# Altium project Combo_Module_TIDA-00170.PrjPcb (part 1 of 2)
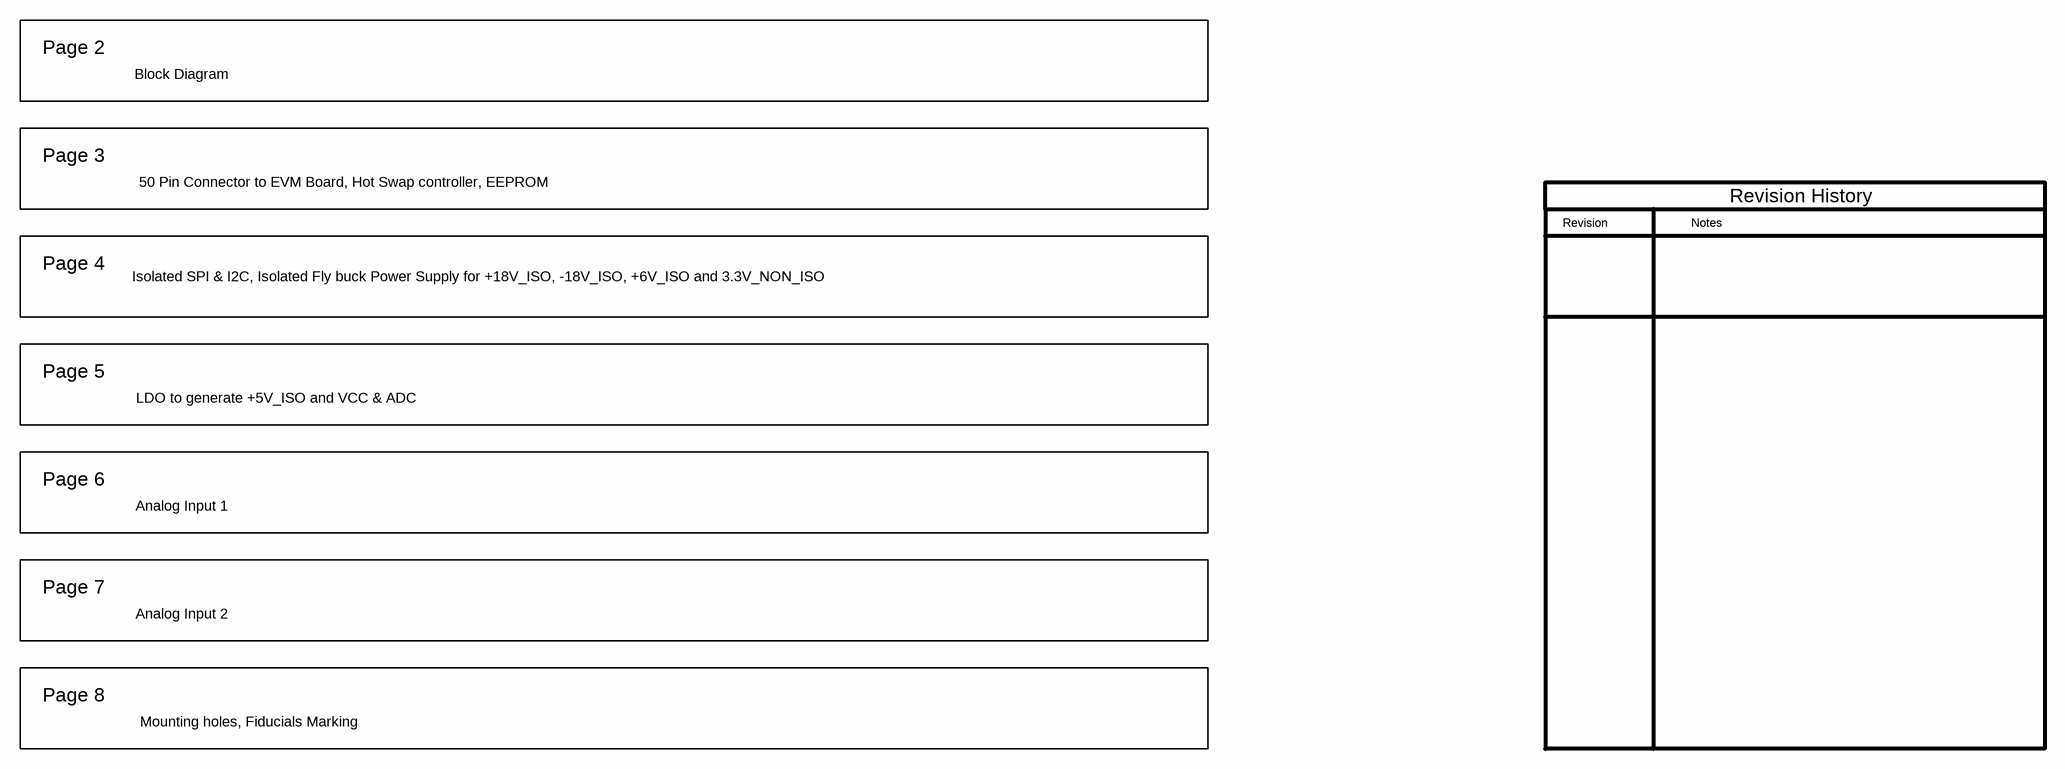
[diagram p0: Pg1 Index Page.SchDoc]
CopyrightYear: 2014; PCB_Rev: E1; PRJ_Customer: Public Release; PRJ_Engineer: Amol Gadkari; PRJ_Number: TIDA-00170; PRJ_Title: Analog Input Output Module; SCH_Rev: E1; TechSupport: http://www.ti.com/support
8 sheets, 276 parts. Net scope: flat (ports and power ports of the same name join across sheets).
Board file: TIDA-00170.PcbDoc
Sheets:
  Pg1 Index Page.SchDoc
  Pg2 Block Diagram.SchDoc
  Pg3 Interboard conn, HS & EEPROM.SchDoc
  Pg4 ISO Power Supply, I2C & SPI Isolators.SchDoc
  Pg5 LDO.SchDoc
  Pg6 ADC.SchDoc
  Pg8 Analog Output.SchDoc
  Pg9 Hardware.SchDoc

## Sheet Pg1 Index Page.SchDoc
size 431 x 279 mm; Date: Not shown in title block; ApprovedBy: Not shown in title block; CheckedBy: Not shown in title block; Author: Not shown in title block; CompanyName: Not shown in title block; Engineer: Not shown in title block; Organization: Not shown in title block; Address1: Not shown in title block; Address2: Not shown in title block; Address3: Not shown in title block; Address4: Not shown in title block; DocumentNumber: 1; Revision: Use project parameter SCH_Rev; SheetNumber: 1; SheetTotal: 8; PageSetup: Record=PageOptions|CenterHorizontal=True|CenterVertical=True|PrintScale=0.62|XCorrection=1.00|YCorrection=1.00|PrintKind=0|BorderSize=5000000|LeftOffset=0|BottomOffset=0|Orientation=2|PaperLength=1000|PaperWidth=1000|Scale=100|PaperSource=15|PrintQuality=600|MediaType=1|DitherType=10|PaperKind=Letter|PrintScaleMode=1

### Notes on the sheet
- Page 2
- Block Diagram
- Page 3
- 50 Pin Connector to EVM Board, Hot Swap controller, EEPROM
- Revision History
- Page 4
- Revision
- Notes
- Isolated SPI & I2C, Isolated Fly buck Power Supply for +18V_ISO, -18V_ISO, +6V_ISO and 3.3V_NON_ISO
- Page 5
- LDO to generate +5V_ISO and VCC & ADC
- Page 6
- Analog Input 1
- Page 7
- Analog Input 2
- Page 8
- Mounting holes, Fiducials Marking

## Sheet Pg2 Block Diagram.SchDoc
size 431 x 279 mm; Date: Not shown in title block; ApprovedBy: Not shown in title block; CheckedBy: Not shown in title block; Author: Not shown in title block; CompanyName: Not shown in title block; Engineer: Not shown in title block; Organization: Not shown in title block; Address1: Not shown in title block; Address2: Not shown in title block; Address3: Not shown in title block; Address4: Not shown in title block; DocumentNumber: 2; Revision: Use project parameter SCH_Rev; SheetNumber: 2; SheetTotal: 8; PageSetup: Record=PageOptions|CenterHorizontal=True|CenterVertical=True|PrintScale=1.00|XCorrection=1.00|YCorrection=1.00|PrintKind=0|BorderSize=5000000|LeftOffset=0|BottomOffset=0|Orientation=2|PaperLength=1000|PaperWidth=1000|Scale=100|PaperSource=15|PrintQuality=600|MediaType=1|DitherType=10|PaperKind=Letter|PrintScaleMode=1
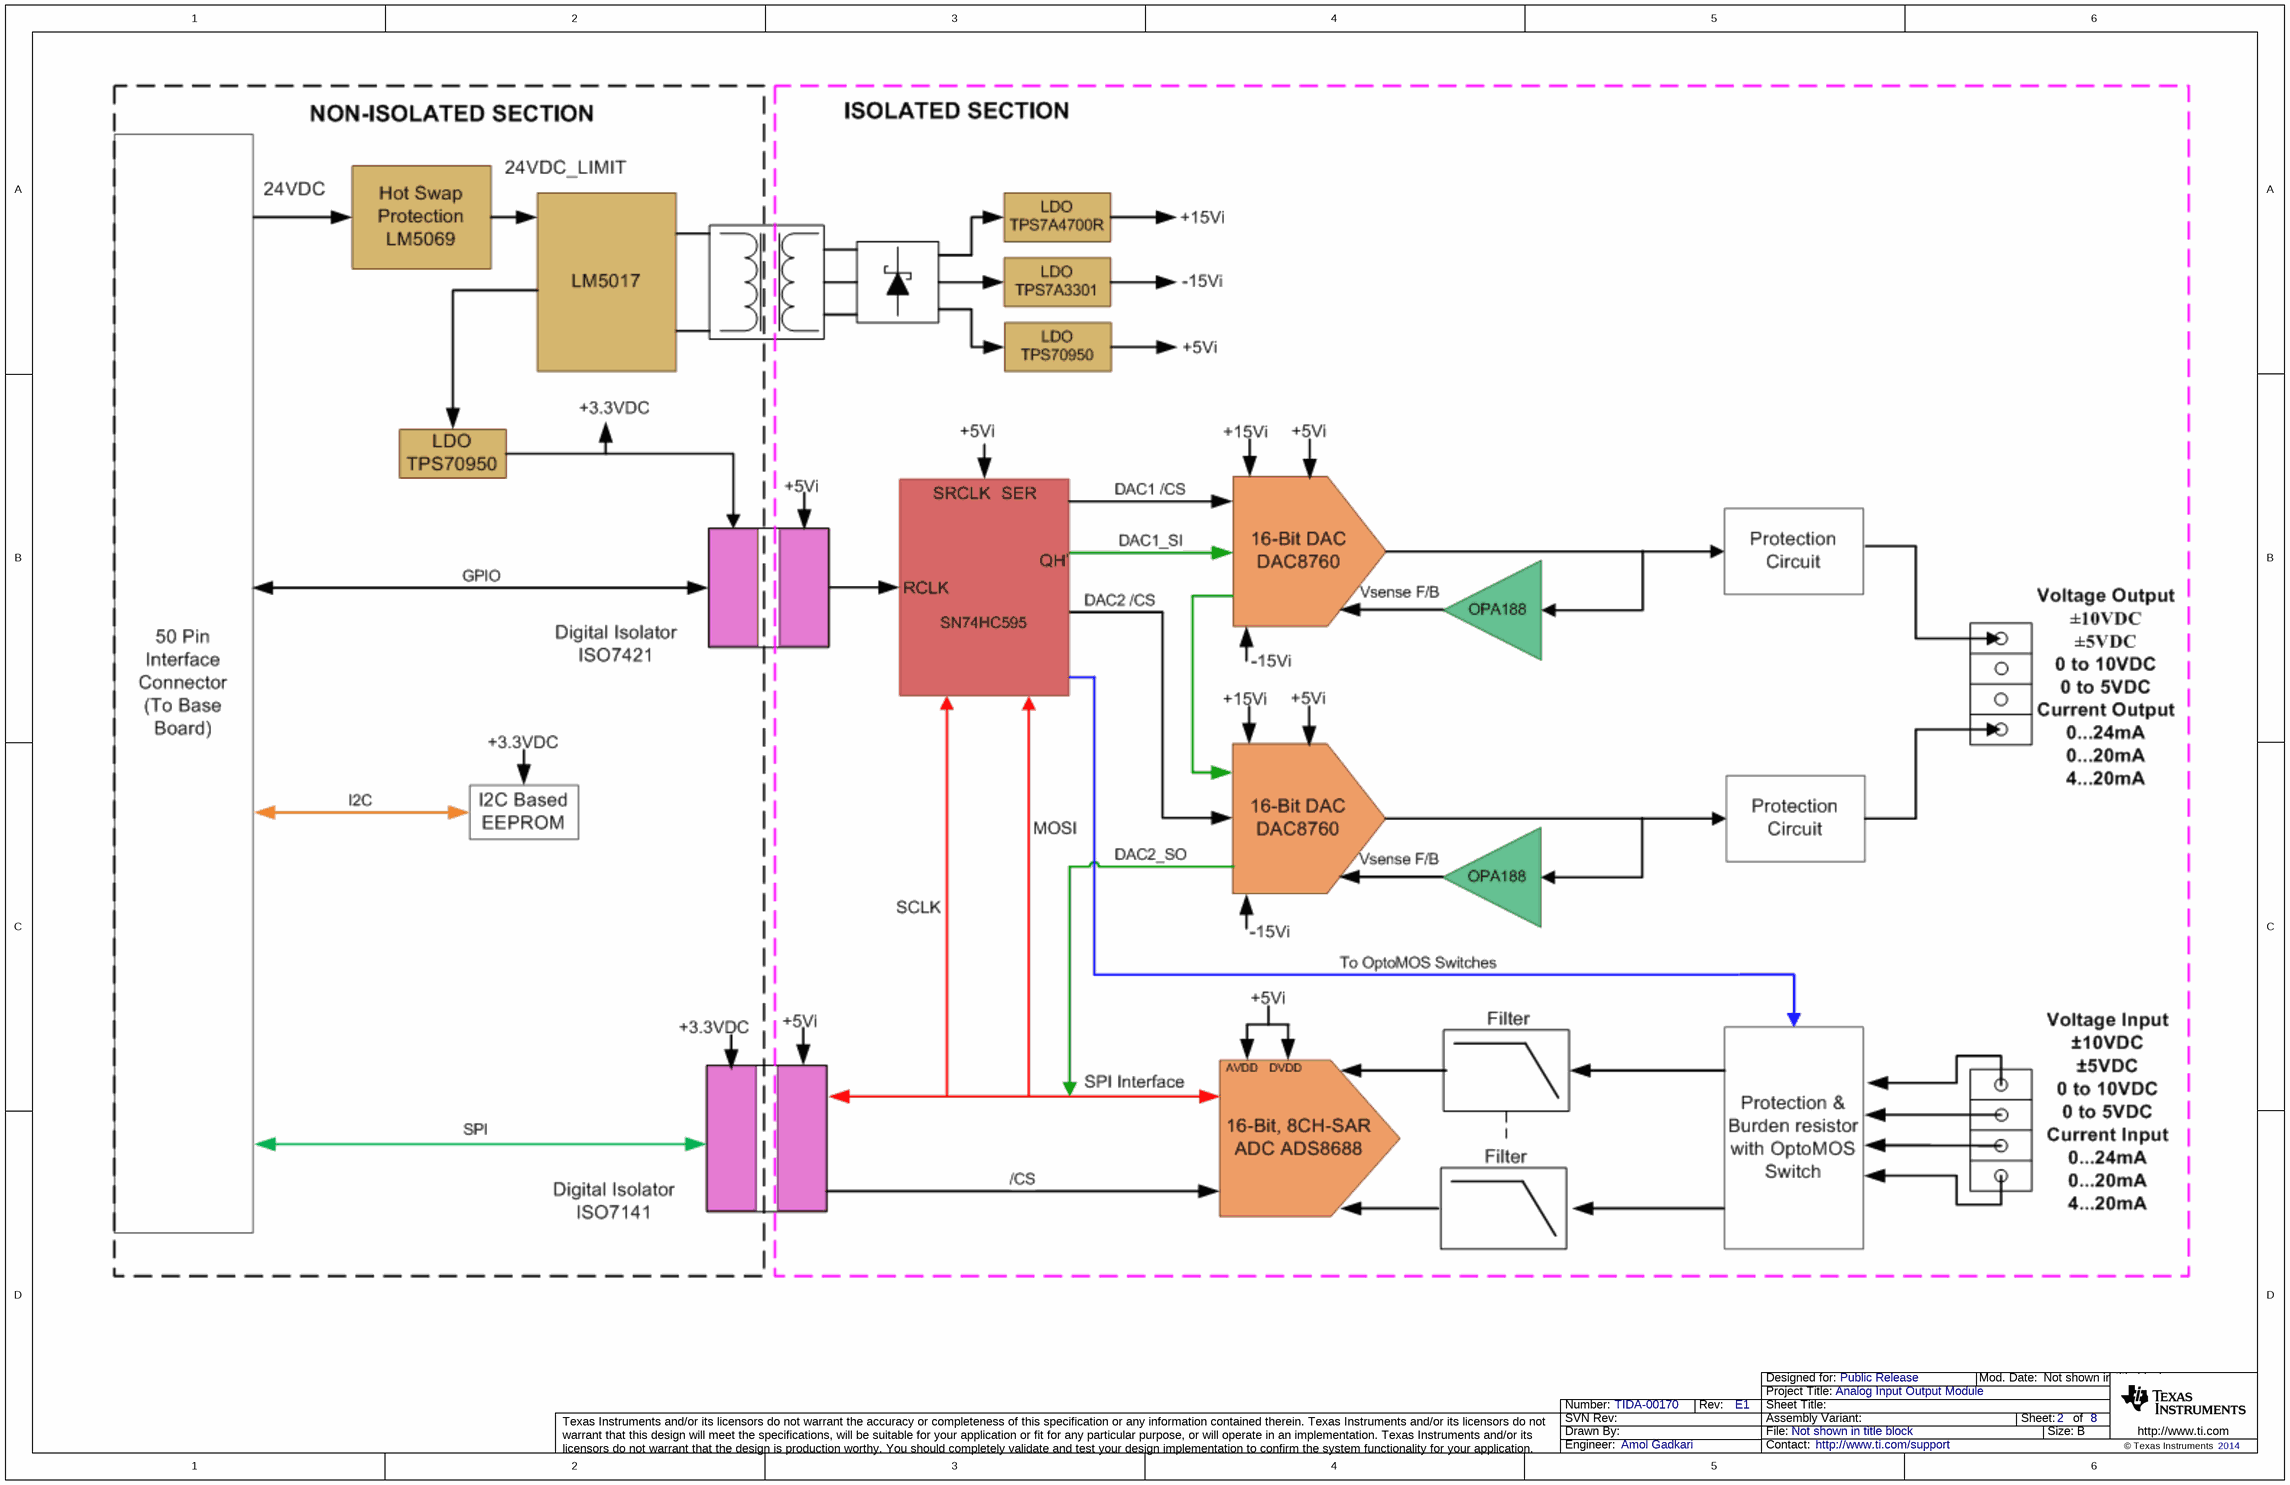
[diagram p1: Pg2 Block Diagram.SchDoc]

## Sheet Pg3 Interboard conn, HS & EEPROM.SchDoc
size 431 x 279 mm; Date: Not shown in title block; ApprovedBy: Not shown in title block; CheckedBy: Not shown in title block; Author: Not shown in title block; CompanyName: Not shown in title block; Engineer: Not shown in title block; Organization: Not shown in title block; Address1: Not shown in title block; Address2: Not shown in title block; Address3: Not shown in title block; Address4: Not shown in title block; DocumentNumber: 3; Revision: Use project parameter SCH_Rev; SheetNumber: 3; SheetTotal: 8; PageSetup: Record=PageOptions|CenterHorizontal=True|CenterVertical=True|PrintScale=1.00|XCorrection=1.00|YCorrection=1.00|PrintKind=0|BorderSize=5000000|LeftOffset=0|BottomOffset=0|Orientation=2|PaperLength=1000|PaperWidth=1000|Scale=100|PaperSource=15|PrintQuality=600|MediaType=1|DitherType=10|PaperKind=Letter|PrintScaleMode=1
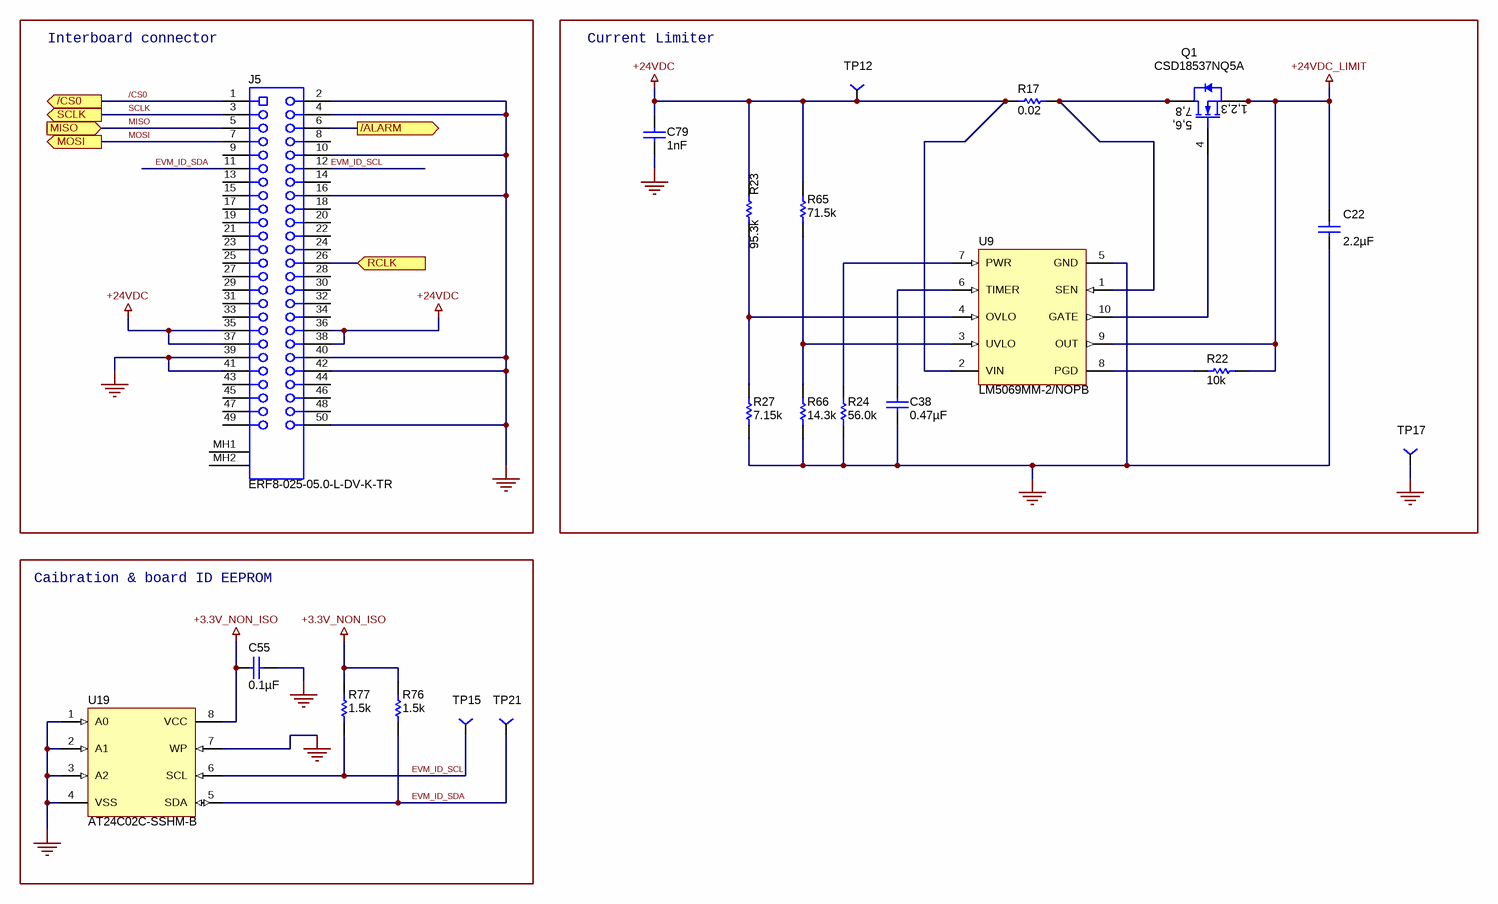
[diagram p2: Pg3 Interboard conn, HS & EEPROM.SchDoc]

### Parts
C22  ValueDisplayed: 2.2µF  [1210]  (hidden comment: GRM32ER72A225KA35L)
C38  ValueDisplayed: 0.47µF  [0603]  (hidden comment: UMK107ABJ474KA-T)
C55  ValueDisplayed: 0.1µF  [0603]  (hidden comment: C0603C104K5RACTU)
C79  ValueDisplayed: 1nF  [0603]  (hidden comment: 06031C102MAT2A)
J5  ERF8-025-05.0-L-DV-K-TR  [CONN_ERF8-025-05_0-L-DV-L-TR]
Q1  CSD18537NQ5A  [TRANS_NexFET_Q5A]
R17  value 0.02  [1206]  (hidden comment: PRL1632-R020-F-T1)
R22  value 10k  [0603]  (hidden comment: CRCW060310K0JNEA)
R23  value 95.3k  [0603]  (hidden comment: CRCW060395K3FKEA)
R24  value 56.0k  [0603]  (hidden comment: RG1608P-563-B-T5)
R27  value 7.15k  [0603]  (hidden comment: CRCW06037K15FKEA)
R65  value 71.5k  [0603]  (hidden comment: CRCW060371K5FKEA)
R66  value 14.3k  [0603]  (hidden comment: CRCW060314K3FKEA)
R76  value 1.5k  [0402]  (hidden comment: CRCW04021K50JNED)
R77  value 1.5k  [0402]  (hidden comment: CRCW04021K50JNED)
TP12  TP-040_RND  [TP1_PD40_D0.5_S50]  (value not drawn)
TP15  TP-040_RND  [TP1_PD40_D0.5_S50]  (value not drawn)
TP17  TP-040_RND  [TP1_PD40_D0.5_S50]  (value not drawn)
TP21  TP-040_RND  [TP1_PD40_D0.5_S50]  (value not drawn)
U9  LM5069MM-2/NOPB  [MUB10A_N]
U19  AT24C02C-SSHM-B  [SOIC-8]

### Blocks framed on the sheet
Interboard connector: J5
Current Limiter: C22 C38 C79 Q1 R17 R22-R24 R27 R65 R66 TP12 TP17 U9
Caibration & board ID EEPROM: C55 R76 R77 TP15 TP21 U19

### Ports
/ALARM (out), /CS0 (out), MISO (in), MOSI (out), RCLK (in), SCLK (out)

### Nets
+3.3V_NON_ISO: C55.2 R76.1 R77.1 U19.8(VCC)
+24VDC: C79.1 J5.35 J5.36 J5.37 J5.38 R17.1 R23.2 R65.2 TP12.1 U9.2(VIN)
+24VDC_LIMIT: C22.1 Q1.1(S) Q1.2(S) Q1.3(S) R22.2 U9.9(OUT)
GND: C22.2 C38.2 C55.1 C79.2 J5.2 J5.4 J5.10 J5.16 J5.39 J5.40 J5.41 J5.42 J5.50 R24.1 R27.1 R66.1 TP17.1 U9.5(GND) U19.1(A0) U19.2(A1) U19.3(A2) U19.4(VSS) U19.7(WP)
/ALARM: J5.6 ; port /ALARM
/CS0: J5.1 ; port /CS0
EVM_ID_SCL: J5.12 R77.2 TP15.1 U19.6(SCL)
EVM_ID_SDA: J5.11 R76.2 TP21.1 U19.5(SDA)
MISO: J5.5 ; port MISO
MOSI: J5.7 ; port MOSI
RCLK: J5.26 ; port RCLK
SCLK: J5.3 ; port SCLK
NetC38_1: C38.1 U9.6(TIMER)
NetQ1_4: Q1.4(G) U9.10(GATE)
NetQ1_5: Q1.5(D) Q1.6(D) Q1.7(D) Q1.8(D) Q1.9(D) R17.2 U9.1(SEN)
NetR22_1: R22.1 U9.8(PGD)
NetR23_1: R23.1 R27.2 U9.4(OVLO)
NetR24_2: R24.2 U9.7(PWR)
NetR65_1: R65.1 R66.2 U9.3(UVLO)

Not connected (* = marked no-connect by the designer): J5 8 9 13 14 15 17 18 19 20 21 22 23 24 25 27 28 29 30 31 32 33 34 43 44 45 46 47 48 49 MH1(51) MH2(52)

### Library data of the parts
C22 = GRM32ER72A225KA35L: CAP, CERM, 2.2uF, 100V, +/-10%, X7R, 1210; Manufacturer: MuRata; Polarized: N; CompType: Capacitor; U/M: EA; Cap_F: 0.0000022; Tolerance_%: 10; ESR_Ohm: 0.007; Value1: 0.007 ohm; VDC_V: 100; IRMS_A: 4.4; TaMin_C: -55; TaMax_C: 125
C38 = UMK107ABJ474KA-T: CAP, CERM, 0.47uF, 50V, 10%, X5R, 0603; Manufacturer: Taiyo Yuden; Polarized: N; CompType: Capacitor; Cap_F: 0.00000047; Tolerance_%: 10; VDC_V: 50
C55 = C0603C104K5RACTU: CAP, CERM, 0.1uF, 50V, +/-10%, X7R, 0603; Manufacturer: Kemet; Polarized: N; CompType: Capacitor; U/M: EA; Cap_F: 0.0000001; Tolerance_%: 10; Value1: Unknown; VDC_V: 50; TaMin_C: -55; TaMax_C: 125
C79 = 06031C102MAT2A: CAP, CERM, 1000pF, 100V, +/-20%, X7R, 0603; Manufacturer: AVX; Polarized: N; CompType: Capacitor; U/M: EA; Cap_F: 0.000000001; Tolerance_%: 20; ESR_Ohm: 0.276; Value1: 0.276 ohm; VDC_V: 100; TaMin_C: -55; TaMax_C: 125
J5 = ERF8-025-05.0-L-DV-K-TR: Receptacle, 0.8mm, 25x2, SMT; Manufacturer: Samtec; SymbolCreator: a0412235; CompType: Connector; U/M: EA
Q1 = CSD18537NQ5A: MOSFET, N-CH, 60V, 50A, SON 5x6mm; Manufacturer: Texas Instruments; Alternate Manufacturer: None; U/M: EA; ChType: N; VdsMax_V: 60; Value1: 0.036 ohm; Rdson45_Ohm: 0.036; Value2: 14 nC; QgTyp_nC: 14; Vgs_V: 20; IdsMax_A: 50
R17 = PRL1632-R020-F-T1: RES, 0.02 ohm, 1%, 1W, 1206; Manufacturer: Susumu Co Ltd; CompType: Resistor; Value_Code: R020; Tolerance_%: 1; TempCo: 100 ppm/C; EIA_Code: E96; U/M: EA
R22 = CRCW060310K0JNEA: RES, 10k ohm, 5%, 0.1W, 0603; Manufacturer: Vishay-Dale; CompType: Resistor; Res_ohm: 10000; Value_Code: 10k0; Tolerance_%: 5; Power_W: 0.1; VDC_V: 75; TempCo: 200 ppm/C; EIA_Code: E24; U/M: EA
R23 = CRCW060395K3FKEA: RES, 95.3k ohm, 1%, 0.1W, 0603; Manufacturer: Vishay-Dale; CompType: Resistor; Res_ohm: 95300; Value_Code: 95k3; Tolerance_%: 1; Power_W: 0.1; VDC_V: 75; TempCo: 100 ppm/C; EIA_Code: E96; U/M: EA
R24 = RG1608P-563-B-T5: RES, 56.0k ohm, 0.1%, 0.1W, 0603; Manufacturer: Susumu Co Ltd; CompType: Resistor; Res_ohm: 56000; Value_Code: 56k0; Tolerance_%: 0.1; VDC_V: 75; TempCo: 25 ppm/C; U/M: EA
R27 = CRCW06037K15FKEA: RES, 7.15k ohm, 1%, 0.1W, 0603; Manufacturer: Vishay-Dale; CompType: Resistor; Res_ohm: 7150; Value_Code: 7k15; Tolerance_%: 1; Power_W: 0.1; VDC_V: 75; TempCo: 100 ppm/C; EIA_Code: E96; U/M: EA
R65 = CRCW060371K5FKEA: RES, 71.5k ohm, 1%, 0.1W, 0603; Manufacturer: Vishay-Dale; CompType: Resistor; Res_ohm: 71500; Value_Code: 71k5; Tolerance_%: 1; Power_W: 0.1; VDC_V: 75; TempCo: 100 ppm/C; EIA_Code: E96; U/M: EA
R66 = CRCW060314K3FKEA: RES, 14.3k ohm, 1%, 0.1W, 0603; Manufacturer: Vishay-Dale; CompType: Resistor; Res_ohm: 14300; Value_Code: 14k3; Tolerance_%: 1; Power_W: 0.1; VDC_V: 75; TempCo: 100 ppm/C; EIA_Code: E96; U/M: EA
R76 R77 = CRCW04021K50JNED: RES, 1.5k ohm, 5%, 0.063W, 0402; Manufacturer: Vishay-Dale; CompType: Resistor; Res_ohm: 1500; Value_Code: 1k50; Tolerance_%: 5; Power_W: 0.063; VDC_V: 50; TempCo: 200 ppm/C; EIA_Code: E24; U/M: EA
TP12 TP15 TP17 TP21 = TP-040_RND: Test Point 40mil pad 20mil drill; Manufacturer: STD; Description: Test Point, O.040 Hole; Value: STD
U9 = LM5069MM-2/NOPB: Positive High Voltage Hot Swap / Inrush Current Controller with Power Limiting, 10-pin MSOP, Pb-Free; Manufacturer: National Semiconductor; PackageTopMarking: ZXTT*SNBB; PowerWise: N; CompType: MiscPower
U19 = AT24C02C-SSHM-B: IC, EEPROM, 2KBIT, 1MHZ, SOIC-8; Manufacturer: Atmel; SymbolCreator: a0411947

## Sheet Pg4 ISO Power Supply, I2C & SPI Isolators.SchDoc
size 431 x 279 mm; Date: Not shown in title block; ApprovedBy: Not shown in title block; CheckedBy: Not shown in title block; Author: Not shown in title block; CompanyName: Not shown in title block; Engineer: Not shown in title block; Organization: Not shown in title block; Address1: Not shown in title block; Address2: Not shown in title block; Address3: Not shown in title block; Address4: Not shown in title block; DocumentNumber: 4; Revision: Use project parameter SCH_Rev; SheetNumber: 4; SheetTotal: 8; PageSetup: Record=PageOptions|CenterHorizontal=True|CenterVertical=True|PrintScale=0.62|XCorrection=1.00|YCorrection=1.00|PrintKind=0|BorderSize=5000000|LeftOffset=0|BottomOffset=0|Orientation=2|PaperLength=1000|PaperWidth=1000|Scale=100|PaperSource=15|PrintQuality=600|MediaType=1|DitherType=10|PaperKind=Letter|PrintScaleMode=1
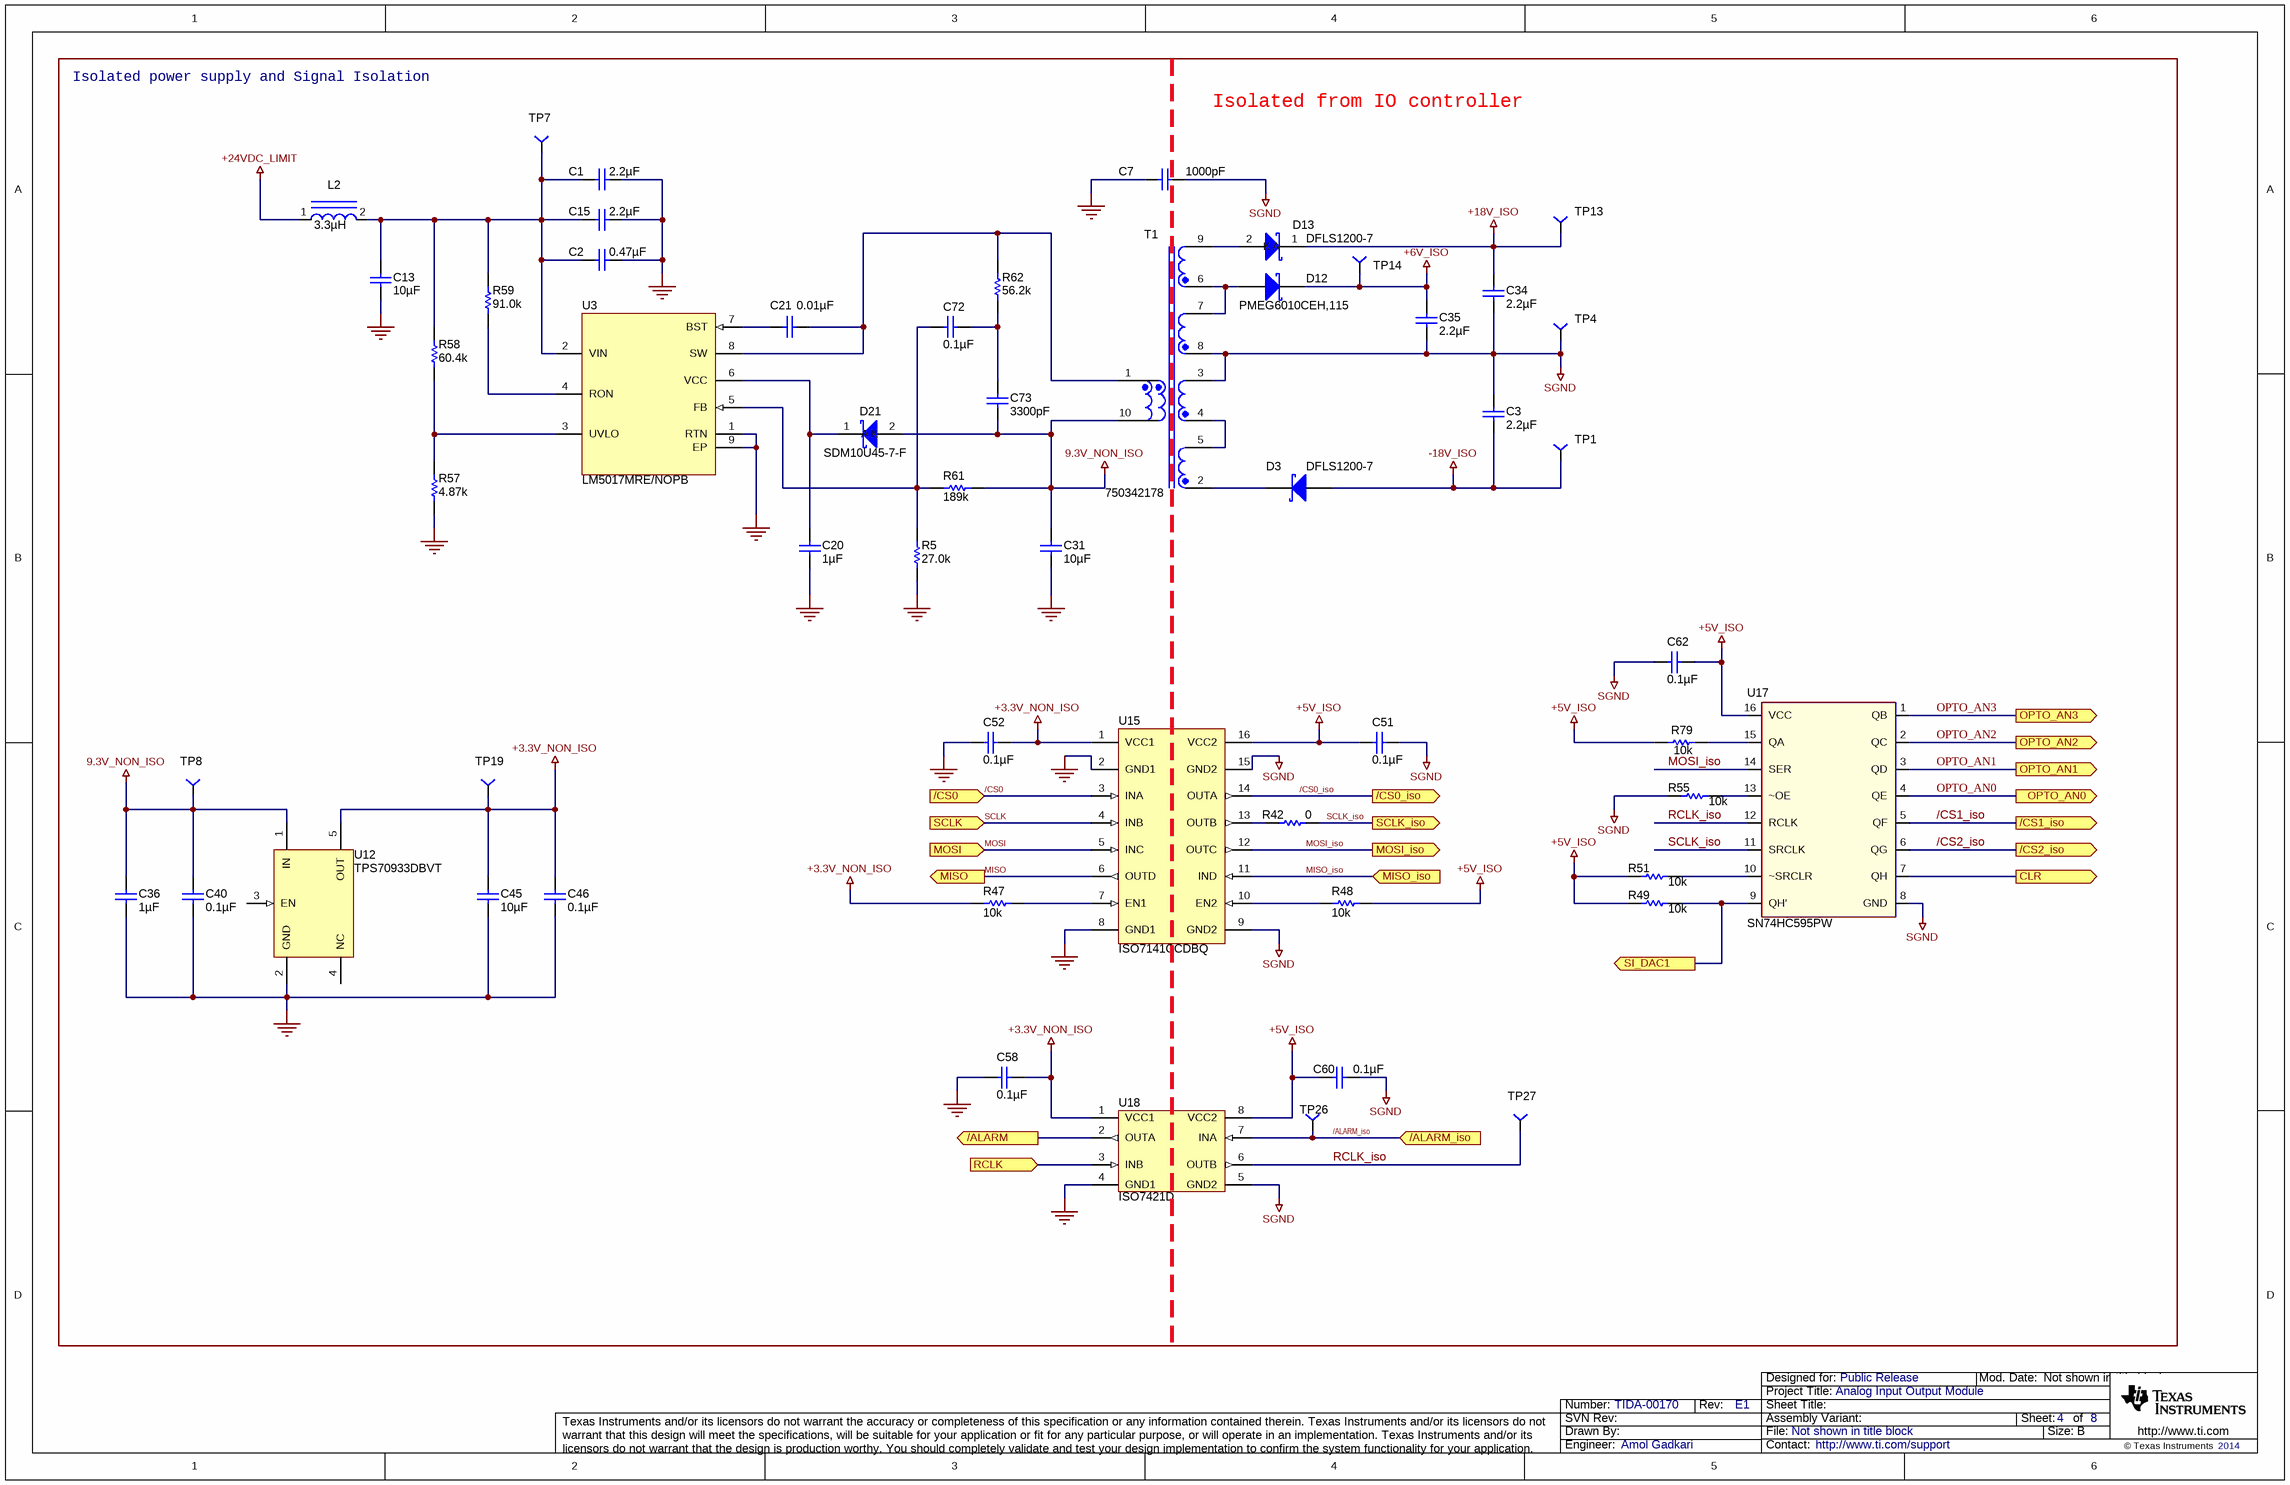
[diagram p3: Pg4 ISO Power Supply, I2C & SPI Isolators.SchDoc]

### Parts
C1  ValueDisplayed: 2.2µF  [1210]  (hidden comment: GRM32ER72A225KA35L)
C2  ValueDisplayed: 0.47µF  [1206]  (hidden comment: GRM31MR72A474KA35L)
C3  ValueDisplayed: 2.2µF  [0805_HV]  (hidden comment: GRM21BR71E225KA73L)
C7  value 1000pF  [1206]  (hidden comment: 202R18W102KV4E)
C13  ValueDisplayed: 10µF  [1210]  (hidden comment: GRM32ER71H106KA12L)
C15  ValueDisplayed: 2.2µF  [1210]  (hidden comment: GRM32ER72A225KA35L)
C20  ValueDisplayed: 1µF  [0603]  (hidden comment: GRM188R61H105KAALD)
C21  ValueDisplayed: 0.01µF  [0603]  (hidden comment: 06031C103JAT2A)
C31  ValueDisplayed: 10µF  [1210]  (hidden comment: GMK325AB7106MM-T)
C34  ValueDisplayed: 2.2µF  [0805_HV]  (hidden comment: GRM21BR71E225KA73L)
C35  ValueDisplayed: 2.2µF  [0805_HV]  (hidden comment: GRM21BR71E225KA73L)
C36  ValueDisplayed: 1µF  [0805]  (hidden comment: 08055C105KAT2A)
C40  ValueDisplayed: 0.1µF  [0603]  (hidden comment: C0603C104K5RACTU)
C45  ValueDisplayed: 10µF  [0805]  (hidden comment: 0805YD106MAT2A)
C46  ValueDisplayed: 0.1µF  [0603]  (hidden comment: C0603C104K5RACTU)
C51  ValueDisplayed: 0.1µF  [0603]  (hidden comment: C0603C104K5RACTU)
C52  ValueDisplayed: 0.1µF  [0603]  (hidden comment: C0603C104K5RACTU)
C58  ValueDisplayed: 0.1µF  [0603]  (hidden comment: C0603C104K5RACTU)
C60  ValueDisplayed: 0.1µF  [0603]  (hidden comment: C0603C104K5RACTU)
C62  ValueDisplayed: 0.1µF  [0603]  (hidden comment: C0603C104K5RACTU)
C72  ValueDisplayed: 0.1µF  [0603]  (hidden comment: GRM188R72A104KA35D)
C73  ValueDisplayed: 3300pF  [0603]  (hidden comment: 06031C332JAT2A)
D3  DFLS1200-7  [powerDI123]
D12  PMEG6010CEH,115  [SOD-123F]
D13  DFLS1200-7  [powerDI123]
D21  SDM10U45-7-F  [SOD-523]
L2  3.3µH  [IND_B82422H]
R5  value 27.0k  [0603]  (hidden comment: RC0603FR-0727KL)
R42  value 0  [0402]  (hidden comment: RC0402JR-070RL)
R47  value 10k  [0402]  (hidden comment: CRCW040210K0JNED)
R48  value 10k  [0402]  (hidden comment: CRCW040210K0JNED)
R49  value 10k  [0402]  (hidden comment: CRCW040210K0JNED)
R51  value 10k  [0402]  (hidden comment: CRCW040210K0JNED)
R55  value 10k  [0402]  (hidden comment: CRCW040210K0JNED)
R57  value 4.87k  [0603]  (hidden comment: RC0603FR-074K87L)
R58  value 60.4k  [0603]  (hidden comment: RT0603BRD0760K4L)
R59  value 91.0k  [0603]  (hidden comment: RC0603FR-0791KL)
R61  value 189k  [0603]  (hidden comment: RT0603BRD07189KL)
R62  value 56.2k  [0603]  (hidden comment: RT0603BRD0756K2L)
R79  value 10k  [0402]  (hidden comment: CRCW040210K0JNED)
T1  750342178  [WURTH_750313995]
TP1  TP1_PD40_D0.5_S50  [TP1_PD40_D0.5_S50]  (value not drawn)
TP4  TP1_PD40_D0.5_S50  [TP1_PD40_D0.5_S50]  (value not drawn)
TP7  TP1_PD40_D0.5_S50  [TP1_PD40_D0.5_S50]  (value not drawn)
TP8  TP1_PD40_D0.5_S50  [TP1_PD40_D0.5_S50]  (value not drawn)
TP13  TP1_PD40_D0.5_S50  [TP1_PD40_D0.5_S50]  (value not drawn)
TP14  TP1_PD40_D0.5_S50  [TP1_PD40_D0.5_S50]  (value not drawn)
TP19  TP1_PD40_D0.5_S50  [TP1_PD40_D0.5_S50]  (value not drawn)
TP26  TP1_PD40_D0.5_S50  [TP1_PD40_D0.5_S50]  (value not drawn)
TP27  TP1_PD40_D0.5_S50  [TP1_PD40_D0.5_S50]  (value not drawn)
U3  LM5017MRE/NOPB  [DDA0008B_N]
U12  TPS70933DBVT  [DBV0005A_N]
U15  ISO7141CCDBQ  [DBQ0016A_N]
U17  SN74HC595PW  [PW16]
U18  ISO7421D  [D0008A_N]

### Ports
/ALARM (out), /ALARM_iso (in), /CS0 (in), /CS0_iso (out), /CS1_iso (out), /CS2_iso (out), CLR (out), MISO (out), MISO_iso (in), MOSI (in), MOSI_iso (out), OPTO_AN0 (out), OPTO_AN1 (out), OPTO_AN2 (out), OPTO_AN3 (out), RCLK (in), SCLK (in), SCLK_iso (out), SI_DAC1 (out)

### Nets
9.3V_NON_ISO: C31.1 C36.1 C40.1 C73.2 D21.2(A) R61.2 T1.10 TP8.1 U12.1(IN)
+3.3V_NON_ISO: C45.1 C46.1 C52.2 C58.2 R47.1 TP19.1 U12.5(OUT) U15.1(VCC1) U18.1(VCC1)
+5V_ISO: C51.1 C60.1 C62.2 R48.2 R49.1 R51.1 R79.2 U15.16(VCC2) U17.16(VCC) U18.8(VCC2)
+6V_ISO: C35.1 D12.1(K) TP14.1
+18V_ISO: C34.1 D13.1(K) TP13.1
+24VDC_LIMIT: L2.1
-18V_ISO: C3.2 D3.2(A) TP1.1
GND: C1.1 C2.1 C7.1 C13.2 C15.1 C20.2 C31.2 C36.2 C40.2 C45.2 C46.2 C52.1 C58.1 R5.1 R57.1 U3.1(RTN) U3.9(EP) U12.2(GND) U15.2(GND1) U15.8(GND1) U18.4(GND1)
SGND: C3.1 C7.2 C34.2 C35.2 C51.2 C60.2 C62.1 R55.1 T1.3 T1.8 TP4.1 U15.9(GND2) U15.15(GND2) U17.8(GND) U18.5(GND2)
/ALARM: U18.2(OUTA) ; port /ALARM
/ALARM_iso: TP26.1 U18.7(INA) ; port /ALARM_iso
/CS0: U15.3(INA) ; port /CS0
/CS0_iso: U15.14(OUTA) ; port /CS0_iso
/CS1_iso: U17.5(QF) ; port /CS1_iso
/CS2_iso: U17.6(QG) ; port /CS2_iso
CLR: U17.7(QH) ; port CLR
MISO: U15.6(OUTD) ; port MISO
MISO_iso: U15.11(IND) ; port MISO_iso
MOSI: U15.5(INC) ; port MOSI
MOSI_iso: U15.12(OUTC) U17.14(SER) ; port MOSI_iso
OPTO_AN0: U17.4(QE) ; port OPTO_AN0
OPTO_AN1: U17.3(QD) ; port OPTO_AN1
OPTO_AN2: U17.2(QC) ; port OPTO_AN2
OPTO_AN3: U17.1(QB) ; port OPTO_AN3
RCLK: U18.3(INB) ; port RCLK
RCLK_iso: TP27.1 U17.12(RCLK) U18.6(OUTB)
SCLK: U15.4(INB) ; port SCLK
SCLK_iso: R42.2 U17.11(SRCLK) ; port SCLK_iso
SI_DAC1: R49.2 U17.9(QH') ; port SI_DAC1
NetC1_2: C1.2 C2.2 C13.1 C15.2 L2.2 R58.2 R59.2 TP7.1 U3.2(VIN)
NetC20_1: C20.1 D21.1(K) U3.6(VCC)
NetC21_1: C21.1 U3.7(BST)
NetC21_2: C21.2 R62.2 T1.1 U3.8(SW)
NetC72_1: C72.1 C73.1 R62.1
NetC72_2: C72.2 R5.2 R61.1 U3.5(FB)
NetD3_1: D3.1(K) T1.2
NetD12_2: D12.2(A) T1.6 T1.7
NetD13_2: D13.2(A) T1.9
NetR42_1: R42.1 U15.13(OUTB)
NetR47_2: R47.2 U15.7(EN1)
NetR48_1: R48.1 U15.10(EN2)
NetR51_2: R51.2 U17.10(~SRCLR)
NetR55_2: R55.2 U17.13(~OE)
NetR57_2: R57.2 R58.1 U3.3(UVLO)
NetR59_1: R59.1 U3.4(RON)
NetR79_1: R79.1 U17.15(QA)
NetT1_4: T1.4 T1.5

Not connected (* = marked no-connect by the designer): U12 3(EN) 4(NC)

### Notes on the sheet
- Isolated power supply and Signal Isolation
- Isolated from IO controller

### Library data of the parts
C1 C15 = GRM32ER72A225KA35L: as C22 on sheet Pg3 Interboard conn, HS & EEPROM
C2 = GRM31MR72A474KA35L: CAP, CERM, 0.47uF, 100V, +/-10%, X7R, 1206; Manufacturer: MuRata; Polarized: N; CompType: Capacitor; U/M: EA; Cap_F: 0.00000047; Tolerance_%: 10; Value1: Unknown; VDC_V: 100; TaMin_C: -55; TaMax_C: 125
C3 C34 C35 = GRM21BR71E225KA73L: CAP, CERM, 2.2uF, 25V, +/-10%, X7R, 0805; Manufacturer: MuRata; Polarized: N; CompType: Capacitor; U/M: EA; Cap_F: 0.0000022; Tolerance_%: 10; ESR_Ohm: 0.005; Value1: 0.005 ohm; VDC_V: 25; TaMin_C: -55; TaMax_C: 125; Cap_Case: 0805
C7 = 202R18W102KV4E: CAP, CERM, 1000pF, 2KV 10% X7R 1206; Manufacturer: Johanson Dielectrics Inc; Polarized: N; CompType: Capacitor; Cap_F: 0.000000001; Tolerance_%: 0
C13 = GRM32ER71H106KA12L: CAP, CERM, 10uF, 50V, +/-10%, X7R, 1210; Manufacturer: MuRata; Polarized: N; CompType: Capacitor; U/M: EA; Cap_F: 0.00001; Tolerance_%: 10; Value1: Unknown; VDC_V: 50; TaMin_C: -55; TaMax_C: 125
C20 = GRM188R61H105KAALD: CAP, CERM, 1uF, 50V, +/-10%, X5R, 0603; Manufacturer: MuRata; Polarized: N; CompType: Capacitor; U/M: EA; Cap_F: 0.000001; Tolerance_%: 10; Value1: Unknown; VDC_V: 50; TaMin_C: -55; TaMax_C: 85
C21 = 06031C103JAT2A: CAP, CERM, 0.01uF, 100V, +/-5%, X7R, 0603; Manufacturer: AVX; Polarized: N; CompType: Capacitor; U/M: EA; Cap_F: 0.00000001; Tolerance_%: 5; ESR_Ohm: 0.098; Value1: 0.098 ohm; VDC_V: 100; TaMin_C: -55; TaMax_C: 125
C31 = GMK325AB7106MM-T: CAP, CERM, 10uF, 35V, +/-20%, X7R, 1210; Manufacturer: Taiyo Yuden; Polarized: N; CompType: Capacitor; U/M: EA; Cap_F: 0.00001; Tolerance_%: 20; Value1: Unknown; VDC_V: 35; TaMin_C: -55; TaMax_C: 125
C36 = 08055C105KAT2A: CAP, CERM, 1uF, 50V, +/-10%, X7R, 0805; Manufacturer: AVX; Polarized: N; CompType: Capacitor; U/M: EA; Cap_F: 0.000001; Tolerance_%: 10; Value1: Unknown; VDC_V: 50; TaMin_C: -55; TaMax_C: 125
C40 C46 C51 C52 C58 C60 C62 = C0603C104K5RACTU: as C55 on sheet Pg3 Interboard conn, HS & EEPROM
C45 = 0805YD106MAT2A: CAP, CERM, 10uF, 16V, +/-20%, X5R, 0805; Manufacturer: AVX; Polarized: N; CompType: Capacitor; U/M: EA; Cap_F: 0.00001; Tolerance_%: 20; Value1: Unknown; VDC_V: 16; TaMin_C: -55; TaMax_C: 85
C72 = GRM188R72A104KA35D: CAP, CERM, 0.1uF, 100V, +/-10%, X7R, 0603; Manufacturer: MuRata; Polarized: N; CompType: Capacitor; U/M: EA; Cap_F: 0.0000001; Tolerance_%: 10; Value1: Unknown; VDC_V: 100; TaMin_C: -55; TaMax_C: 125
C73 = 06031C332JAT2A: CAP, CERM, 3300pF, 100V, +/-5%, X7R, 0603; Manufacturer: AVX; Polarized: N; CompType: Capacitor; U/M: EA; Cap_F: 0.0000000033; Tolerance_%: 5; ESR_Ohm: 0.159; Value1: 0.159 ohm; VDC_V: 100; TaMin_C: -55; TaMax_C: 125
D3 D13 = DFLS1200-7: Diode, Schottky, 200V, 1A, PowerDI123; Manufacturer: Diodes Inc.; U/M: EA; Vf_V: 0.85; Value2: 0.85V; Io_A: 1; Vr_V: 200; TJmax_C: 175; RJC_CperW: 7
D12 = PMEG6010CEH,115: Diode, Schottky, 60V, 1A, SOD-123F; Manufacturer: NXP Semiconductor; U/M: EA; Vf_V: 0.57; Value2: 0.57V; Io_A: 1; Vr_V: 60; TJmax_C: 150
D21 = SDM10U45-7-F: Diode, Schottky, 45V, 0.1A, SOD-523; Manufacturer: Diodes Inc.; U/M: EA; Vf_V: 0.58; Value2: 0.58V; Io_A: 0.1; Vr_V: 45; TJmax_C: 125
L2 = IND_ELJEA_SERIES: Inductor, Chip, ±10%; Manufacturer: EPCOS INC.; PartNumber: B82422H1332K; Area: 28000; Description: INDUCTOR 3.3UH 770MA 1210 10%
R5 = RC0603FR-0727KL: RES, 27.0k ohm, 1%, 0.1W, 0603; Manufacturer: Yageo America; CompType: Resistor; Res_ohm: 27000; Value_Code: 27k0; Tolerance_%: 1; Power_W: 0.1; VDC_V: 150; TempCo: 200 ppm/C; U/M: EA
R42 = RC0402JR-070RL: RES, 0 ohm, 5%, 0.063W, 0402; Manufacturer: Yageo America; CompType: Resistor; Value_Code: 0000; Tolerance_%: 5; Power_W: 0.063; VDC_V: 50; TempCo: 200 ppm/C; EIA_Code: E24; U/M: EA
R47-R49 R51 R55 R79 = CRCW040210K0JNED: RES, 10k ohm, 5%, 0.063W, 0402; Manufacturer: Vishay-Dale; CompType: Resistor; Res_ohm: 10000; Value_Code: 10k0; Tolerance_%: 5; Power_W: 0.063; VDC_V: 50; TempCo: 200 ppm/C; EIA_Code: E24; U/M: EA
R57 = RC0603FR-074K87L: RES, 4.87k ohm, 1%, 0.1W, 0603; Manufacturer: Yageo America; CompType: Resistor; Res_ohm: 4870; Value_Code: 4k87; Tolerance_%: 1; Power_W: 0.1; VDC_V: 150; TempCo: 200 ppm/C; EIA_Code: E96; U/M: EA
R58 = RT0603BRD0760K4L: RES, 60.4k ohm, 0.1%, 0.1W, 0603; Manufacturer: Yageo America; CompType: Resistor; Res_ohm: 60400; Value_Code: 60k4; Tolerance_%: 0.1; VDC_V: 75; TempCo: 25 ppm/C; EIA_Code: E192; U/M: EA
R59 = RC0603FR-0791KL: RES, 91.0k ohm, 1%, 0.1W, 0603; Manufacturer: Yageo America; CompType: Resistor; Res_ohm: 91000; Value_Code: 91k0; Tolerance_%: 1; Power_W: 0.1; VDC_V: 150; TempCo: 200 ppm/C; U/M: EA
R61 = RT0603BRD07189KL: RES, 189k ohm, 0.1%, 0.1W, 0603; Manufacturer: Yageo America; CompType: Resistor; Res_ohm: 189000; Tolerance_%: 0.1; VDC_V: 75; TempCo: 25 ppm/C; EIA_Code: E192; U/M: EA
R62 = RT0603BRD0756K2L: RES, 56.2k ohm, 0.1%, 0.1W, 0603; Manufacturer: Yageo America; CompType: Resistor; Res_ohm: 56200; Value_Code: 56k2; Tolerance_%: 0.1; VDC_V: 75; TempCo: 25 ppm/C; EIA_Code: E192; U/M: EA
T1 = 750313995: Transformer, 50uH, SMT; Manufacturer: Wurth Elektronik eiSos; SymbolCreator: a0411947; DCR_Ohm: 0.11; LeakageL: 0.130uH; U/M: EA
TP1 TP4 TP7 TP8 TP13 TP14 TP19 TP26 TP27 = TP-040_RND: as TP12 on sheet Pg3 Interboard conn, HS & EEPROM
U3 = LM5017MRE/NOPB: 100V, 600mA Constant On-Time Synchronous Buck Regulator, DDA0008B; Alternate Manufacturer: None; Manufacturer: Texas Instruments; SymbolCreator: a0412235; CompType: IC; U/M: EA
U12 = TPS70933DBVT: IC REG LDO 3.3V 0.15A SOT23-5; Alternate Manufacturer: None; Manufacturer: Texas Instruments; SymbolCreator: a0411947; U/M: EA
U15 = ISO7141CCDBQ: 4242-VPK Small-Footprint and Low-Power Quad Channels Digital Isolators, DBQ0016A; Alternate Manufacturer: None; Manufacturer: Texas Instruments; SymbolCreator: a0799628; CompType: IC; U/M: EA
U17 = SN74HC595PW: IC, 8-Bit Shift Registers With 3-State Output Registers; Manufacturer: TI; Alternate Manufacturer: None; Area: 103600
U18 = ISO7421D: 1 Mbps Dual Channels, 1 / 1, Digital Isolator, 3.3 V / 5 V, -40 to +105 degC, 8-pin SOIC (D), Green (RoHS & no Sb/Br); Manufacturer: Texas Instruments; Alternate Manufacturer: None; Alternate PartNumber: Equivalent; Datarate(Mbps): 1; Eco-Plan: TBD; Insulation Rating(VRMS): 2500; Prop Delay(Max)(ns): 12; Rating: Catalog; Supply Voltage(s)(V): 3.3, 5; TTL/CMOS Input Threshold: TTL

## Sheet Pg5 LDO.SchDoc
size 431 x 279 mm; Date: Not shown in title block; ApprovedBy: Not shown in title block; CheckedBy: Not shown in title block; Author: Not shown in title block; CompanyName: Not shown in title block; Engineer: Not shown in title block; Organization: Not shown in title block; Address1: Not shown in title block; Address2: Not shown in title block; Address3: Not shown in title block; Address4: Not shown in title block; DocumentNumber: 5; Revision: Use project parameter SCH_Rev; SheetNumber: 5; SheetTotal: 8; PageSetup: Record=PageOptions|CenterHorizontal=True|CenterVertical=True|PrintScale=1.00|XCorrection=1.00|YCorrection=1.00|PrintKind=0|BorderSize=5000000|LeftOffset=0|BottomOffset=0|Orientation=2|PaperLength=1000|PaperWidth=1000|Scale=100|PaperSource=15|PrintQuality=600|MediaType=1|DitherType=10|PaperKind=Letter|PrintScaleMode=1
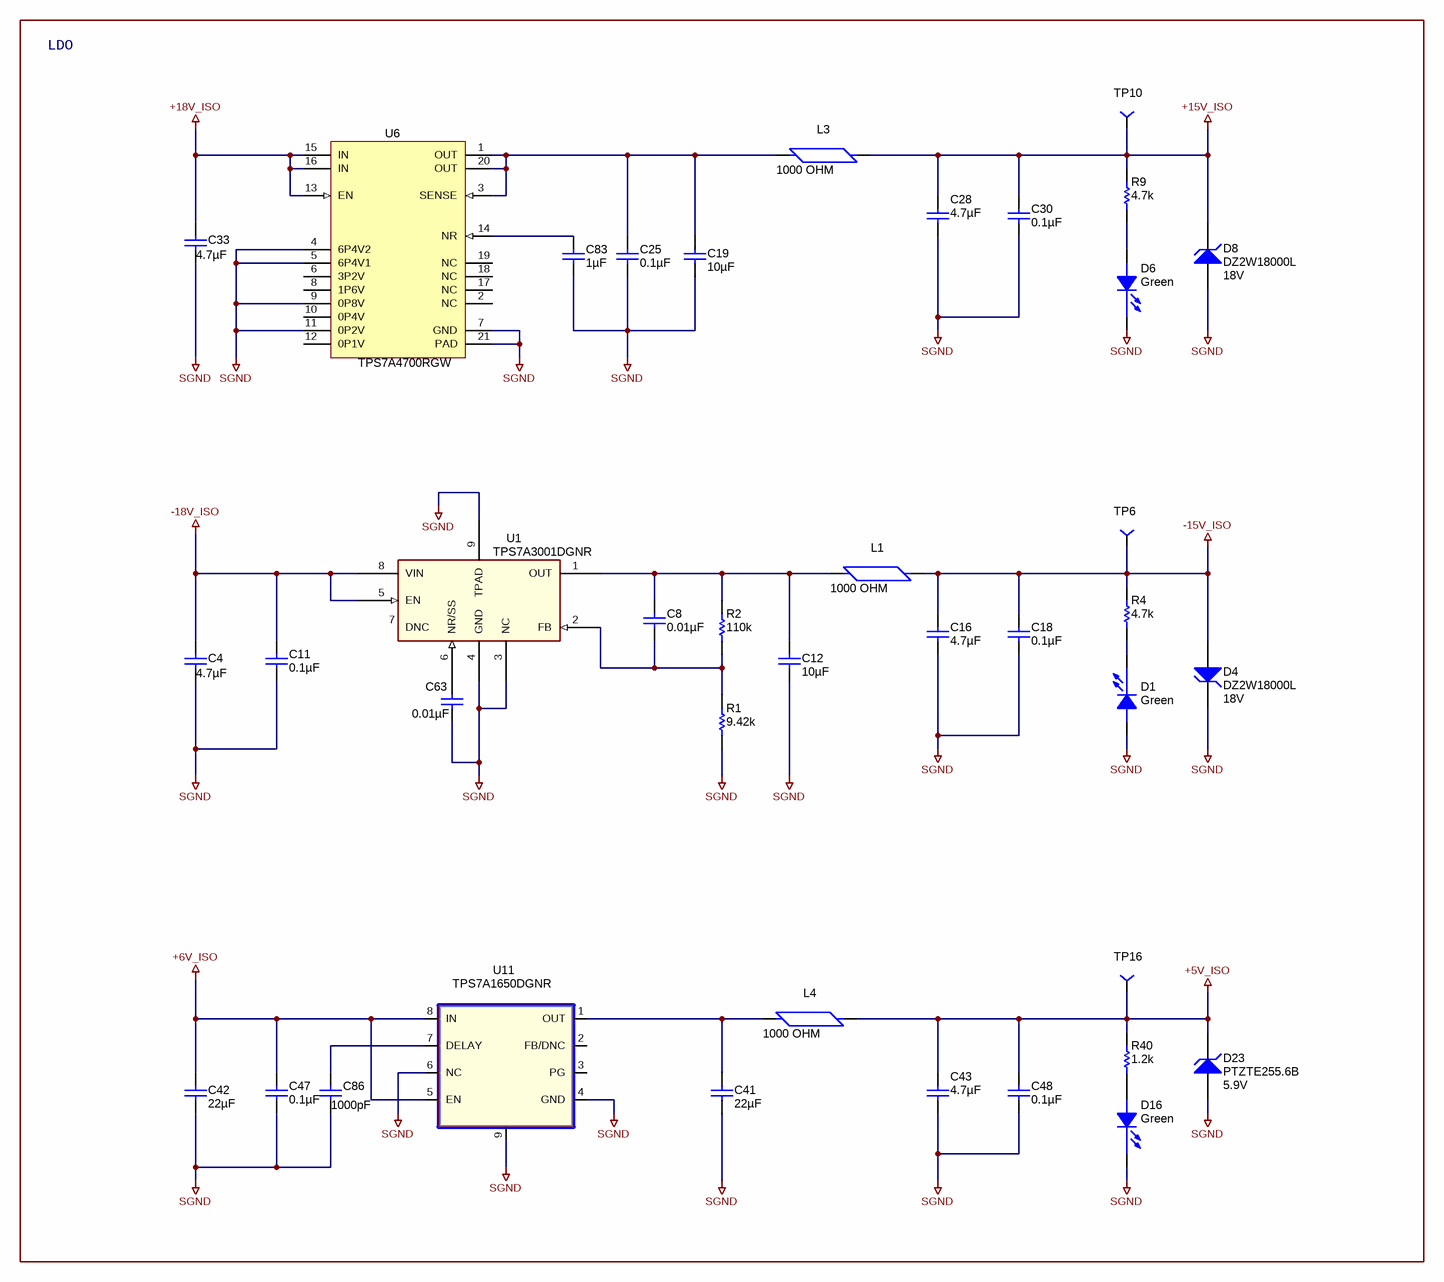
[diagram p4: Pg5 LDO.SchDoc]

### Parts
C4  ValueDisplayed: 4.7µF  [1206]  (hidden comment: GRM31CR71H475KA12L)
C8  ValueDisplayed: 0.01µF  [0603]  (hidden comment: 06031C103JAT2A)
C11  ValueDisplayed: 0.1µF  [0603]  (hidden comment: 06035C104KAT2A)
C12  ValueDisplayed: 10µF  [1206]  (hidden comment: GRM31CR71E106KA12L)
C16  ValueDisplayed: 4.7µF  [0805_HV]  (hidden comment: C2012X5R1H475K125AB)
C18  ValueDisplayed: 0.1µF  [0603]  (hidden comment: 06035C104KAT2A)
C19  ValueDisplayed: 10µF  [1206]  (hidden comment: GRM31CR71E106KA12L)
C25  ValueDisplayed: 0.1µF  [0603]  (hidden comment: 06035C104KAT2A)
C28  ValueDisplayed: 4.7µF  [0805_HV]  (hidden comment: C2012X5R1H475K125AB)
C30  ValueDisplayed: 0.1µF  [0603]  (hidden comment: 06035C104KAT2A)
C33  ValueDisplayed: 4.7µF  [1206]  (hidden comment: GRM31CR71H475KA12L)
C41  ValueDisplayed: 22µF  [0805_HV]  (hidden comment: GRM21BR61C226ME44)
C42  ValueDisplayed: 22µF  [0805_HV]  (hidden comment: GRM21BR61C226ME44)
C43  ValueDisplayed: 4.7µF  [0805_HV]  (hidden comment: C2012X5R1H475K125AB)
C47  ValueDisplayed: 0.1µF  [0603]  (hidden comment: 06035C104KAT2A)
C48  ValueDisplayed: 0.1µF  [0603]  (hidden comment: 06035C104KAT2A)
C63  ValueDisplayed: 0.01µF  [0603]  (hidden comment: 06031C103JAT2A)
C83  ValueDisplayed: 1µF  [0603]  (hidden comment: C1608X7R1E105K080AB)
C86  ValueDisplayed: 1000pF  [0603]  (hidden comment: 06031C102JAT2A)
D1  value Green  [LED0603AA]  (hidden comment: LED_LG L29K-G2J1-24-Z)
D4  DZ2W18000L  value 18V  [SOD-123]
D6  value Green  [LED0603AA]  (hidden comment: LED_LG L29K-G2J1-24-Z)
D8  DZ2W18000L  value 18V  [SOD-123]
D16  value Green  [LED0603AA]  (hidden comment: LED_LG L29K-G2J1-24-Z)
D23  PTZTE255.6B  value 5.9V  [powerDI123]
L1  1000 OHM  [FB0603]
L3  1000 OHM  [FB0603]
L4  1000 OHM  [FB0603]
R1  value 9.42k  [0402]  (hidden comment: TNPW04029K42BEED)
R2  value 110k  [0402]  (hidden comment: CRCW0402110KFKED)
R4  value 4.7k  [0603]  (hidden comment: CRCW06034K70JNEA)
R9  value 4.7k  [0603]  (hidden comment: CRCW06034K70JNEA)
R40  value 1.2k  [0402]  (hidden comment: CRCW04021K20JNED)
TP6  TP-038  [TP1_PD40_D0.5_S50]  (value not drawn)
TP10  TP-038  [TP1_PD40_D0.5_S50]  (value not drawn)
TP16  TP-038  [TP1_PD40_D0.5_S50]  (value not drawn)
U1  TPS7A3001DGNR  [MSOP8(DGN)]
U6  TPS7A4700RGW  [RGW0020A]
U11  TPS7A1650DGNR  [DGN_8P]

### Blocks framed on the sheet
LDO: C4 C8 C11 C12 C16 C18 C19 C25 C28 C30 C33 C41-C43 C47 C48 C63 C83 C86 D1 D4 D6 D8 D16 D23 L1 L3 L4 R1 R2 R4 R9 R40 TP6 TP10 TP16 U1 U6 U11

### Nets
+5V_ISO: C43.1 C48.2 D23.1(K) L4.2 R40.1 TP16.1
+6V_ISO: C42.1 C47.2 U11.5(EN) U11.8(IN)
+15V_ISO: C28.1 C30.2 D8.1(K) L3.2 R9.1 TP10.1
+18V_ISO: C33.1 U6.13(EN) U6.15(IN) U6.16(IN)
-15V_ISO: C16.2 C18.2 D4.2(A) L1.2 R4.1 TP6.1
-18V_ISO: C4.1 C11.2 U1.5(EN) U1.8(VIN)
SGND: C4.2 C11.1 C12.2 C16.1 C18.1 C19.2 C25.1 C28.2 C30.1 C33.2 C41.2 C42.2 C43.2 C47.1 C48.1 C63.2 C83.2 C86.2 D1.2(A) D4.1(K) D6.1(C) D8.2(A) D16.1(C) D23.2(A) R1.2 U1.3(NC) U1.4(GND) U1.9(TPAD) U6.4(6P4V2) U6.5(6P4V1) U6.7(GND) U6.9(0P8V) U6.11(0P2V) U6.21(PAD) U11.4(GND) U11.6(NC) U11.9
NetC8_1: C8.1 C12.1 L1.1 R2.1 U1.1(OUT)
NetC8_2: C8.2 R1.1 R2.2 U1.2(FB)
NetC19_1: C19.1 C25.2 L3.1 U6.1(OUT) U6.3(SENSE) U6.20(OUT)
NetC41_1: C41.1 L4.1 U11.1(OUT)
NetC63_1: C63.1 U1.6(NR/SS)
NetC83_1: C83.1 U6.14(NR)
NetC86_1: C86.1 U11.7(DELAY)
NetD1_1: D1.1(C) R4.2
NetD6_2: D6.2(A) R9.2
NetD16_2: D16.2(A) R40.2

Not connected (* = marked no-connect by the designer): U1 7(DNC); U6 2(NC) 6(3P2V) 8(1P6V) 10(0P4V) 12(0P1V) 17(NC) 18(NC) 19(NC); U11 2(FB/DNC) 3(PG)

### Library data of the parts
C4 C33 = GRM31CR71H475KA12L: CAP, CERM, 4.7uF, 50V, +/-10%, X7R, 1206; Manufacturer: MuRata; Polarized: N; CompType: Capacitor; U/M: EA; Cap_F: 0.0000047; Tolerance_%: 10; Value1: Unknown; VDC_V: 50; TaMin_C: -55; TaMax_C: 125; Cap_Case: 2220
C8 C63 = 06031C103JAT2A: as C21 on sheet Pg4 ISO Power Supply, I2C & SPI Isolators
C11 C18 C25 C30 C47 C48 = 06035C104KAT2A: CAP, CERM, 0.1uF, 50V, +/-10%, X7R, 0603; Manufacturer: AVX; Polarized: N; CompType: Capacitor; U/M: EA; Cap_F: 0.0000001; Tolerance_%: 10; Value1: Unknown; VDC_V: 50; TaMin_C: -55; TaMax_C: 125
C12 C19 = GRM31CR71E106KA12L: CAP, CERM, 10uF, 25V, +/-10%, X7R, 1206; Manufacturer: MuRata; Polarized: N; CompType: Capacitor; U/M: EA; Cap_F: 0.00001; Tolerance_%: 10; Value1: Unknown; VDC_V: 25; TaMin_C: -55; TaMax_C: 125; Cap_Case: 2220
C16 C28 C43 = C2012X5R1H475K125AB: CAP, CERM, 4.7uF, 50V, +/-10%, X5R, 0805; Manufacturer: TDK; Polarized: N; CompType: Capacitor; U/M: EA; Cap_F: 0.0000047; Tolerance_%: 10; Value1: Unknown; VDC_V: 50; TaMin_C: -55; TaMax_C: 85; Cap_Case: 0805
C41 C42 = GRM21BR61C226ME44: CAP, CERM, 22uF, 16V, +/-20%, X5R, 0805; Manufacturer: MuRata; Polarized: N; CompType: Capacitor; U/M: EA; Cap_F: 0.000022; Tolerance_%: 20; Value1: Unknown; VDC_V: 16; TaMin_C: -55; TaMax_C: 85; Cap_Case: 0805
C83 = C1608X7R1E105K080AB: CAP, CERM, 1uF, 25V, +/-10%, X7R, 0603; Manufacturer: TDK; Polarized: N; CompType: Capacitor; U/M: EA; Cap_F: 0.000001; Tolerance_%: 10; Value1: Unknown; VDC_V: 25; TaMin_C: -55; TaMax_C: 125
C86 = 06031C102JAT2A: CAP, CERM, 1000pF, 100V, +/-5%, X7R, 0603; Manufacturer: AVX; Polarized: N; CompType: Capacitor; U/M: EA; Cap_F: 0.000000001; Tolerance_%: 5; ESR_Ohm: 0.276; Value1: 0.276 ohm; VDC_V: 100; TaMin_C: -55; TaMax_C: 125
D1 D6 D16 = LED_LG L29K-G2J1-24-Z: LED SmartLED Green 570NM; Manufacturer: OSRAM; SymbolCreator: x0120606
D4 D8 = DZ2W18000L: Diode, Zener, 18V, 1W, SOD-123; Manufacturer: Panasonic
D23 = PTZTE255.6B: DIODE ZENER 5.9V 1W PMDS; Manufacturer: Rohm Semiconductor; U/M: EA; Vz_V: 5.9
L1 L3 L4 = MMZ1608B102C: FERRITE CHIP 1000 OHM 300MA 0603; Manufacturer: TDK Corporation; CompType: Ferrite Bead
R1 = CRCW04029K31FKED: RES, 9.42k ohm, 1%, 0.063W, 0402; Manufacturer: Vishay-Dale; CompType: Resistor; Res_ohm: 9310; Value_Code: 9k42; Tolerance_%: 1; Power_W: 0.063; VDC_V: 50; TempCo: 100 ppm/C; EIA_Code: E96; U/M: EA
R2 = CRCW0402110KFKED: RES, 110k ohm, 1%, 0.063W, 0402; Manufacturer: Vishay-Dale; CompType: Resistor; Res_ohm: 110000; Tolerance_%: 1; Power_W: 0.063; VDC_V: 50; TempCo: 100 ppm/C; EIA_Code: E96; U/M: EA
R4 R9 = CRCW06034K70JNEA: RES, 4.7k ohm, 5%, 0.1W, 0603; Manufacturer: Vishay-Dale; CompType: Resistor; Res_ohm: 4700; Value_Code: 4k70; Tolerance_%: 5; Power_W: 0.1; VDC_V: 75; TempCo: 200 ppm/C; EIA_Code: E24; U/M: EA
R40 = CRCW04021K20JNED: RES, 1.2k ohm, 5%, 0.063W, 0402; Manufacturer: Vishay-Dale; CompType: Resistor; Res_ohm: 1200; Value_Code: 1k20; Tolerance_%: 5; Power_W: 0.063; VDC_V: 50; TempCo: 200 ppm/C; EIA_Code: E24; U/M: EA
TP6 TP10 TP16 = TP-038: Test Point 40mil pad 20mil drill; Manufacturer: STD; Value: STD
U1 = TPS7A3001DGNR: -36V, -200mA, Ultralow-Noise, Negative Linear Regulator; Alternate Manufacturer: None; Manufacturer: Texas Instruments; CompType: IC; SymbolCreator: x0120606
U6 = TPS7A4700RGW: 36-V, 1-A, 4.17-µVRMS, RF LDO Voltage Regulator, RGW0020A; Alternate Manufacturer: None; Manufacturer: Texas Instruments; SymbolCreator: a0412235; CompType: IC; U/M: EA
U11 = TPS7A16XXDGN: IC, 60-V, 6-A IQ, 100-mA, LDO Voltage Regulator with Enable and Power-Good Functions; Manufacturer: TI; Alternate Manufacturer: None; Area: 35250

## Sheet Pg6 ADC.SchDoc
size 431 x 279 mm; Date: Not shown in title block; ApprovedBy: Not shown in title block; CheckedBy: Not shown in title block; Author: Not shown in title block; CompanyName: Not shown in title block; Engineer: Not shown in title block; Organization: Not shown in title block; Address1: Not shown in title block; Address2: Not shown in title block; Address3: Not shown in title block; Address4: Not shown in title block; DocumentNumber: 6; Revision: Use project parameter SCH_Rev; SheetNumber: 6; SheetTotal: 8; PageSetup: Record=PageOptions|CenterHorizontal=True|CenterVertical=True|PrintScale=1.00|XCorrection=1.00|YCorrection=1.00|PrintKind=0|BorderSize=5000000|LeftOffset=0|BottomOffset=0|Orientation=2|PaperLength=1000|PaperWidth=1000|Scale=100|PaperSource=15|PrintQuality=600|MediaType=1|DitherType=10|PaperKind=Letter|PrintScaleMode=1
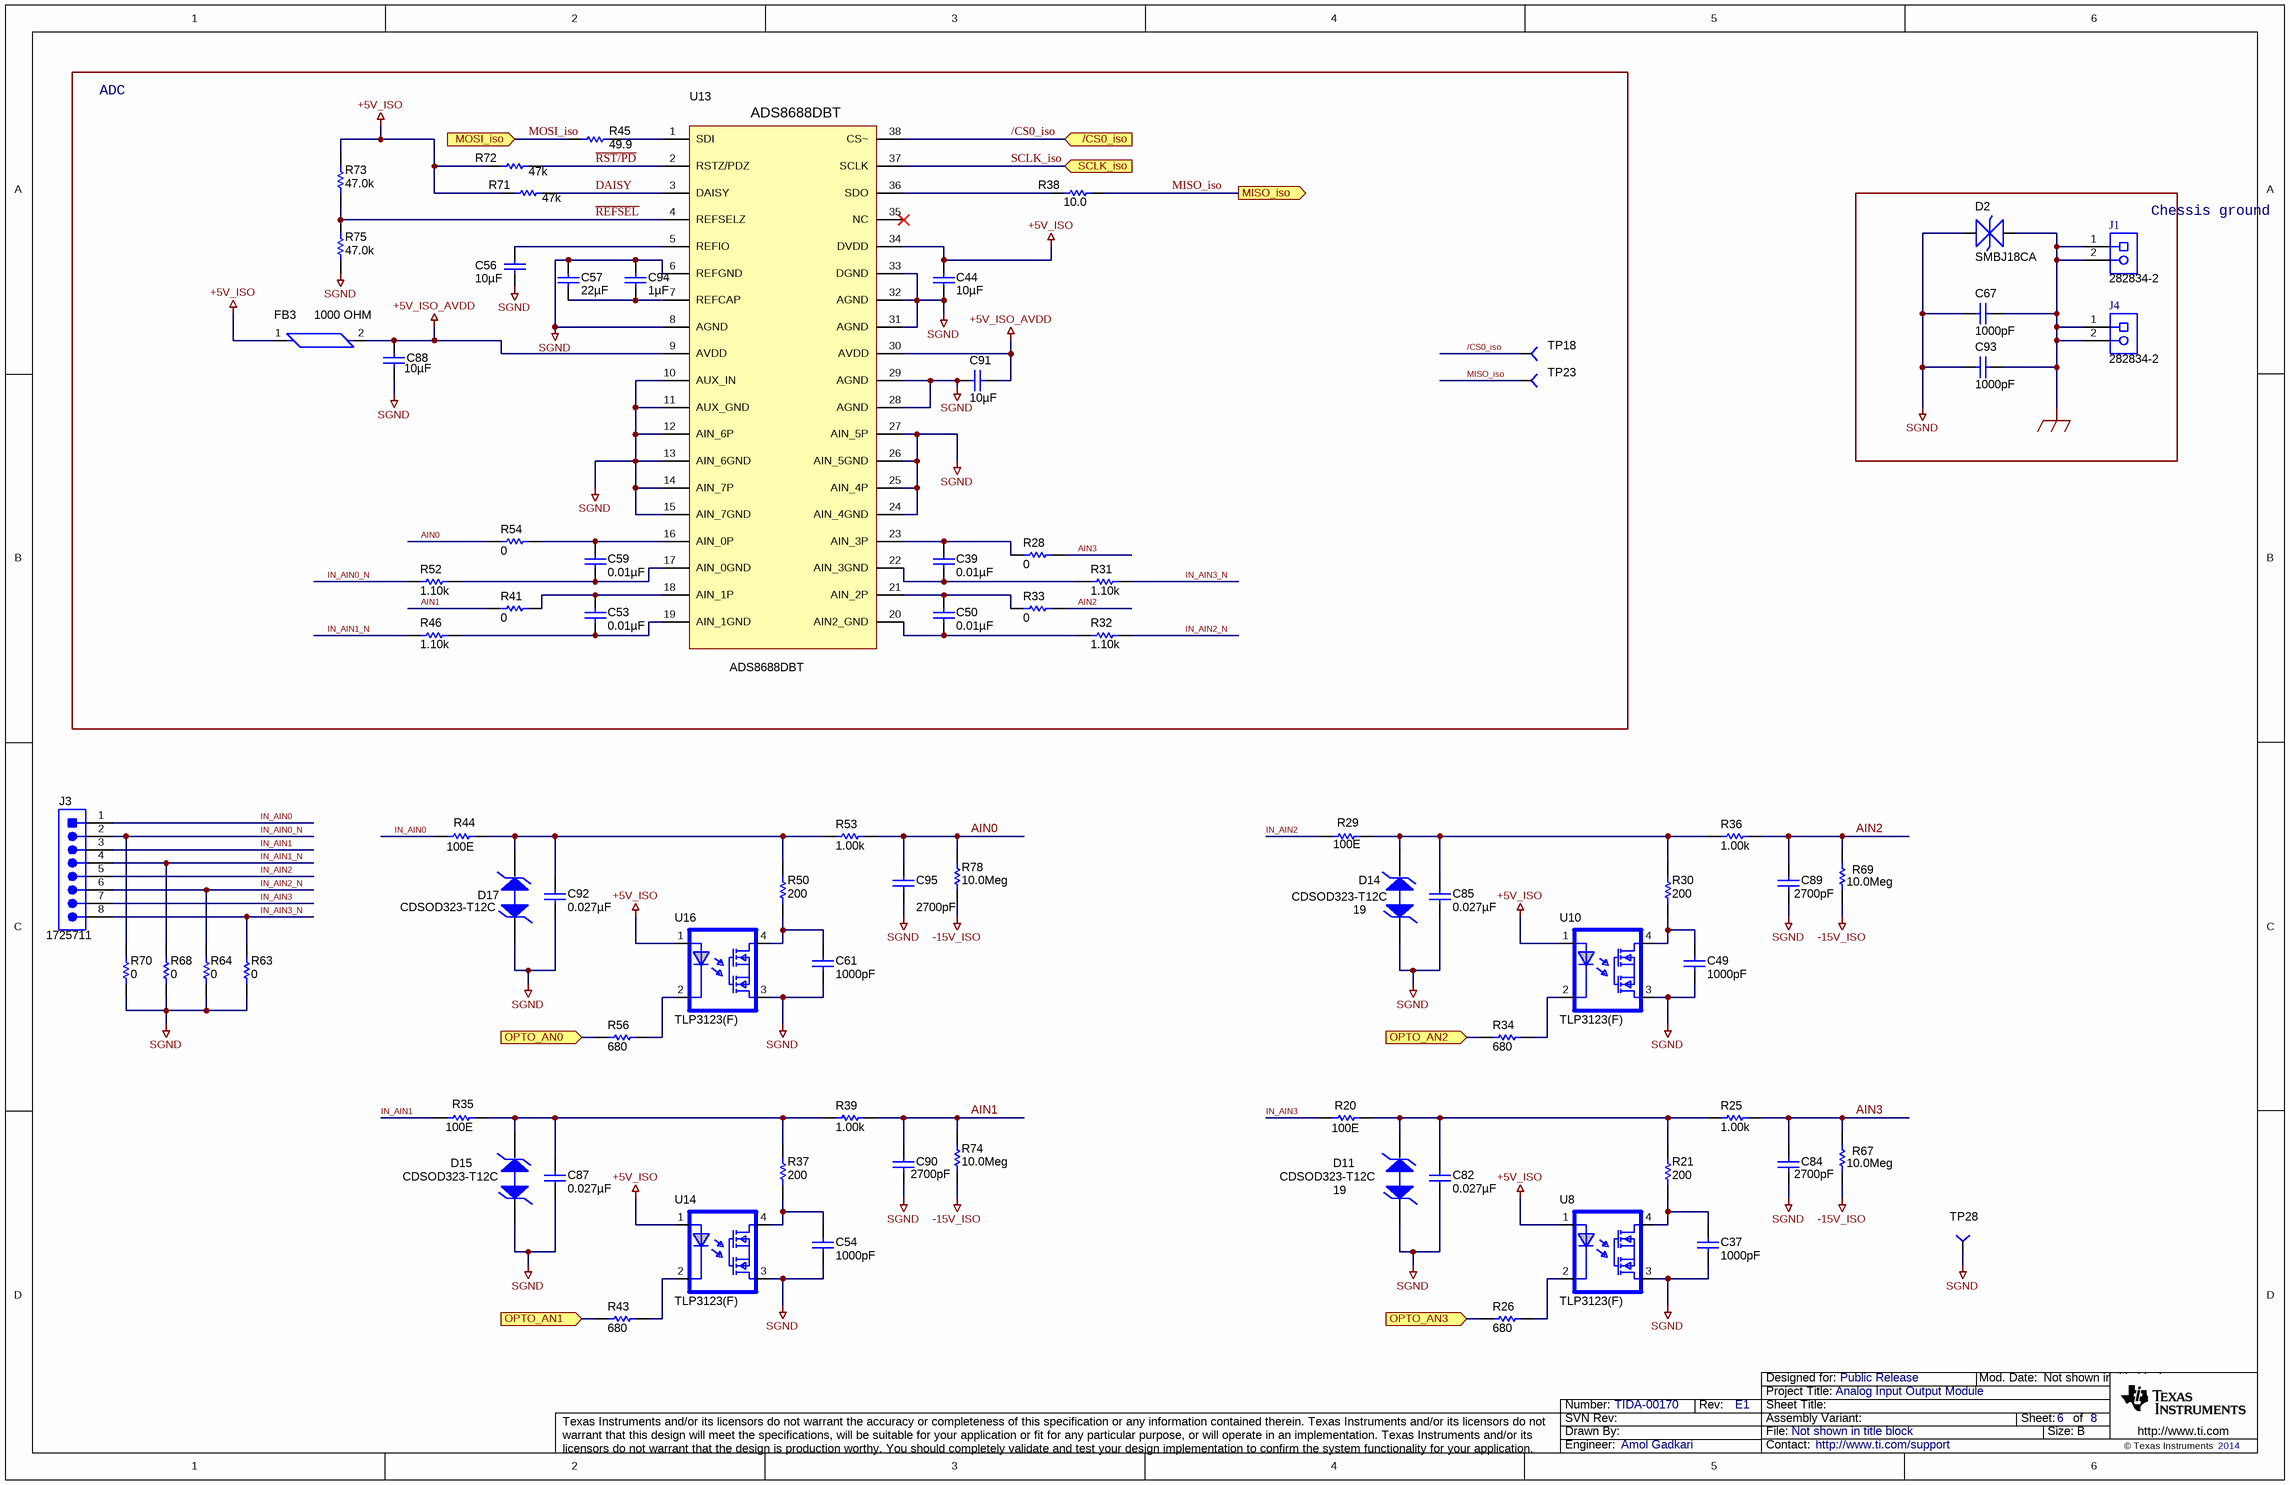
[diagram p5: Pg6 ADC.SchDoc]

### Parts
C37  ValueDisplayed: 1000pF  [0402]  (hidden comment: C1005X7R1H102M)
C39  ValueDisplayed: 0.01µF  [0402]  (hidden comment: GRM155R71H103KA88D)
C44  ValueDisplayed: 10µF  [0603]  (hidden comment: C1608X5R1E106M080AC)
C49  ValueDisplayed: 1000pF  [0402]  (hidden comment: C1005X7R1H102M)
C50  ValueDisplayed: 0.01µF  [0402]  (hidden comment: GRM155R71H103KA88D)
C53  ValueDisplayed: 0.01µF  [0402]  (hidden comment: GRM155R71H103KA88D)
C54  ValueDisplayed: 1000pF  [0402]  (hidden comment: C1005X7R1H102M)
C56  ValueDisplayed: 10µF  [0805_HV]  (hidden comment: 0805YD106MAT2A)
C57  ValueDisplayed: 22µF  [0805_HV]  (hidden comment: C2012X5R1C226K125AC)
C59  ValueDisplayed: 0.01µF  [0402]  (hidden comment: GRM155R71H103KA88D)
C61  ValueDisplayed: 1000pF  [0402]  (hidden comment: C1005X7R1H102M)
C67  value 1000pF  [1206]  (hidden comment: 202R18W102KV4E)
C82  ValueDisplayed: 0.027µF  [1206]  (hidden comment: GRM3195C1H273JA01D)
C84  ValueDisplayed: 2700pF  [0603]  (hidden comment: 06031C272JAT2A)
C85  ValueDisplayed: 0.027µF  [1206]  (hidden comment: GRM3195C1H273JA01D)
C87  ValueDisplayed: 0.027µF  [1206]  (hidden comment: GRM3195C1H273JA01D)
C88  ValueDisplayed: 10µF  [0603]  (hidden comment: EMK107BBJ106MA-T)
C89  ValueDisplayed: 2700pF  [0603]  (hidden comment: 06031C272JAT2A)
C90  ValueDisplayed: 2700pF  [0603]  (hidden comment: 06031C272JAT2A)
C91  ValueDisplayed: 10µF  [0603]  (hidden comment: EMK107BBJ106MA-T)
C92  ValueDisplayed: 0.027µF  [1206]  (hidden comment: GRM3195C1H273JA01D)
C93  value 1000pF  [1206]  (hidden comment: 202R18W102KV4E)
C94  ValueDisplayed: 1µF  [0603]  (hidden comment: EMK107B7105KA-T)
C95  ValueDisplayed: 2700pF  [0603]  (hidden comment: 06031C272JAT2A)
D2  SMBJ18CA  [DIO_SMB_BIAAAA]
D11  CDSOD323-T12C  value 19  [sod-323]
D14  CDSOD323-T12C  value 19  [sod-323]
D15  CDSOD323-T12C  [sod-323]
D17  CDSOD323-T12C  [sod-323]
FB3  1000 OHM  [FB0603]
J1  282834-2  [TEC_282834-2]
J3  1725711  [CONN_1725711]
J4  282834-2  [TEC_282834-2]
R20  value 100E  [1206]  (hidden comment: MMA02040C1000FB300)
R21  value 200  [0805]  (hidden comment: RG2012P-201-B-T5)
R25  value 1.00k  [0603]  (hidden comment: CRCW06031K00FKEA)
R26  value 680  [0402]  (hidden comment: CRCW0402680RJNED)
R28  value 0  [0402]  (hidden comment: CRCW04020000Z0ED)
R29  value 100E  [1206]  (hidden comment: MMA02040C1000FB300)
R30  value 200  [0805]  (hidden comment: RG2012P-201-B-T5)
R31  value 1.10k  [0402]  (hidden comment: CRCW04021K10FKED)
R32  value 1.10k  [0402]  (hidden comment: CRCW04021K10FKED)
R33  value 0  [0402]  (hidden comment: CRCW04020000Z0ED)
R34  value 680  [0402]  (hidden comment: CRCW0402680RJNED)
R35  value 100E  [1206]  (hidden comment: MMA02040C1000FB300)
R36  value 1.00k  [0603]  (hidden comment: CRCW06031K00FKEA)
R37  value 200  [0805]  (hidden comment: RG2012P-201-B-T5)
R38  value 10.0  [0603]  (hidden comment: CRCW060310R0FKEA)
R39  value 1.00k  [0603]  (hidden comment: CRCW06031K00FKEA)
R41  value 0  [0402]  (hidden comment: CRCW04020000Z0ED)
R43  value 680  [0402]  (hidden comment: CRCW0402680RJNED)
R44  value 100E  [1206]  (hidden comment: MMA02040C1000FB300)
R45  value 49.9  [0402]  (hidden comment: CRCW040249R9FKED)
R46  value 1.10k  [0402]  (hidden comment: CRCW04021K10FKED)
R50  value 200  [0805]  (hidden comment: RG2012P-201-B-T5)
R52  value 1.10k  [0402]  (hidden comment: CRCW04021K10FKED)
R53  value 1.00k  [0603]  (hidden comment: CRCW06031K00FKEA)
R54  value 0  [0402]  (hidden comment: CRCW04020000Z0ED)
R56  value 680  [0402]  (hidden comment: CRCW0402680RJNED)
R63  value 0  [1206]  (hidden comment: CRCW12060000Z0EAHP)
R64  value 0  [1206]  (hidden comment: CRCW12060000Z0EAHP)
R67  value 10.0Meg  [0402]  (hidden comment: CRCW040210M0FKED)
R68  value 0  [1206]  (hidden comment: CRCW12060000Z0EAHP)
R69  value 10.0Meg  [0402]  (hidden comment: CRCW040210M0FKED)
R70  value 0  [1206]  (hidden comment: CRCW12060000Z0EAHP)
R71  value 47k  [0402]  (hidden comment: CRCW040247K0JNED)
R72  value 47k  [0402]  (hidden comment: CRCW040247K0JNED)
R73  value 47.0k  [0603]  (hidden comment: RT0603BRD0747KL)
R74  value 10.0Meg  [0402]  (hidden comment: CRCW040210M0FKED)
R75  value 47.0k  [0603]  (hidden comment: RT0603BRD0747KL)
R78  value 10.0Meg  [0402]  (hidden comment: CRCW040210M0FKED)
TP18  TP1_PD40_D0.5_S50  [TP1_PD40_D0.5_S50]  (value not drawn)
TP23  TP1_PD40_D0.5_S50  [TP1_PD40_D0.5_S50]  (value not drawn)
TP28  TP1_PD40_D0.5_S50  [TP1_PD40_D0.5_S50]  (value not drawn)
U8  TLP3123(F)  [SOIC254P700X210-4N]
U10  TLP3123(F)  [SOIC254P700X210-4N]
U13  ADS8688DBT  [DBT0038A_M]
U14  TLP3123(F)  [SOIC254P700X210-4N]
U16  TLP3123(F)  [SOIC254P700X210-4N]

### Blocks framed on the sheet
ADC: C39 C44 C50 C53 C56 C57 C59 C88 C91 C94 FB3 R28 R31-R33 R38 R41 R45 R46 R52 R54 R71-R73 R75 TP18 TP23 U13
Chessis ground: C67 C93 D2 J1 J4

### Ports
/CS0_iso (in), MISO_iso (out), MOSI_iso (in), OPTO_AN0 (in), OPTO_AN1 (in), OPTO_AN2 (in), OPTO_AN3 (in), SCLK_iso (in)

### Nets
+5V_ISO: C44.1 FB3.1 R71.1 R72.1 R73.1 U8.1(Anode) U10.1(Anode) U13.34(DVDD) U14.1(Anode) U16.1(Anode)
+5V_ISO_AVDD: C88.1 C91.1 FB3.2 U13.9(AVDD) U13.30(AVDD)
-15V_ISO: R67.1 R69.1 R74.1 R78.1
GND_EARTH: C67.2 C93.2 D2.2 J1.1 J1.2 J4.1 J4.2
SGND: C37.2 C44.2 C49.2 C54.2 C56.2 C57.1 C61.2 C67.1 C82.2 C84.2 C85.2 C87.2 C88.2 C89.2 C90.2 C91.2 C92.2 C93.1 C94.1 C95.2 D2.1 D11.2 D14.2 D15.2 D17.2 R63.1 R64.1 R68.1 R70.1 R75.2 TP28.1 U8.3(Drain_D1) U10.3(Drain_D1) U13.6(REFGND) U13.8(AGND) U13.10(AUX_IN) U13.11(AUX_GND) U13.12(AIN_6P) U13.13(AIN_6GND) U13.14(AIN_7P) U13.15(AIN_7GND) U13.24(AIN_4GND) U13.25(AIN_4P) U13.26(AIN_5GND) U13.27(AIN_5P) U13.28(AGND) U13.29(AGND) U13.31(AGND) U13.32(AGND) U13.33(DGND) U14.3(Drain_D1) U16.3(Drain_D1)
/CS0_iso: TP18.1 U13.38(CS~) ; port /CS0_iso
~{REFSEL}: R73.2 R75.1 U13.4(REFSELZ)
~{RST/PD}: R72.2 U13.2(RSTZ/PDZ)
AIN0: C95.1 R53.2 R54.1 R78.2
AIN1: C90.1 R39.2 R41.1 R74.2
AIN2: C89.1 R33.2 R36.2 R69.2
AIN3: C84.1 R25.2 R28.2 R67.2
DAISY: R71.2 U13.3(DAISY)
IN_AIN0: J3.1 R44.1
IN_AIN0_N: J3.2 R52.1 R70.2
IN_AIN1: J3.3 R35.1
IN_AIN1_N: J3.4 R46.1 R68.2
IN_AIN2: J3.5 R29.1
IN_AIN2_N: J3.6 R32.2 R64.2
IN_AIN3: J3.7 R20.1
IN_AIN3_N: J3.8 R31.2 R63.2
MISO_iso: R38.2 TP23.1 ; port MISO_iso
MOSI_iso: R45.1 ; port MOSI_iso
OPTO_AN0: R56.1 ; port OPTO_AN0
OPTO_AN1: R43.1 ; port OPTO_AN1
OPTO_AN2: R34.1 ; port OPTO_AN2
OPTO_AN3: R26.1 ; port OPTO_AN3
SCLK_iso: U13.37(SCLK) ; port SCLK_iso
NetC37_1: C37.1 R21.1 U8.4(Drain_D2)
NetC39_1: C39.1 R28.1 U13.23(AIN_3P)
NetC39_2: C39.2 R31.1 U13.22(AIN_3GND)
NetC49_1: C49.1 R30.1 U10.4(Drain_D2)
NetC50_1: C50.1 R33.1 U13.21(AIN_2P)
NetC50_2: C50.2 R32.1 U13.20(AIN2_GND)
NetC53_1: C53.1 R41.2 U13.18(AIN_1P)
NetC53_2: C53.2 R46.2 U13.19(AIN_1GND)
NetC54_1: C54.1 R37.1 U14.4(Drain_D2)
NetC56_1: C56.1 U13.5(REFIO)
NetC57_2: C57.2 C94.2 U13.7(REFCAP)
NetC59_1: C59.1 R54.2 U13.16(AIN_0P)
NetC59_2: C59.2 R52.2 U13.17(AIN_0GND)
NetC61_1: C61.1 R50.1 U16.4(Drain_D2)
NetC82_1: C82.1 D11.1 R20.2 R21.2 R25.1
NetC85_1: C85.1 D14.1 R29.2 R30.2 R36.1
NetC87_1: C87.1 D15.1 R35.2 R37.2 R39.1
NetC92_1: C92.1 D17.1 R44.2 R50.2 R53.1
NetR26_2: R26.2 U8.2(Cathode)
NetR34_2: R34.2 U10.2(Cathode)
NetR38_1: R38.1 U13.36(SDO)
NetR43_2: R43.2 U14.2(Cathode)
NetR45_2: R45.2 U13.1(SDI)
NetR56_2: R56.2 U16.2(Cathode)

Not connected (* = marked no-connect by the designer): U13 35(NC)*

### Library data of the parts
C37 C49 C54 C61 = C1005X7R1H102M: CAP, CERM, 1000pF, 50V, +/-20%, X7R, 0402; Manufacturer: TDK; Polarized: N; CompType: Capacitor; U/M: EA; Cap_F: 0.000000001; Tolerance_%: 20; ESR_Ohm: 0.005; Value1: 0.005 ohm; VDC_V: 50; TaMin_C: -55; TaMax_C: 125
C39 C50 C53 C59 = GRM155R71H103KA88D: CAP, CERM, 0.01uF, 50V, +/-10%, X7R, 0402; Manufacturer: MuRata; Polarized: N; CompType: Capacitor; U/M: EA; Cap_F: 0.00000001; Tolerance_%: 10; Value1: Unknown; VDC_V: 50; TaMin_C: -55; TaMax_C: 125
C44 = C1608X5R1E106M080AC: CAP, CERM, 10uF, 25V, +/-20%, X5R, 0603; Manufacturer: TDK; Polarized: N; CompType: Capacitor; U/M: EA; Cap_F: 0.00001; Tolerance_%: 20; Value1: Unknown; VDC_V: 25; TaMin_C: -55; TaMax_C: 85
C56 = 0805YD106MAT2A: CAP, CERM, 10uF, 16V, +/-20%, X5R, 0805; Manufacturer: AVX; Polarized: N; CompType: Capacitor; U/M: EA; Cap_F: 0.00001; Tolerance_%: 20; Value1: Unknown; VDC_V: 16; TaMin_C: -55; TaMax_C: 85; Cap_Case: 0805
C57 = C2012X5R1C226K125AC: CAP, CERM, 22uF, 16V, +/-10%, X5R, 0805; Manufacturer: TDK; Polarized: N; CompType: Capacitor; U/M: EA; Cap_F: 0.000022; Tolerance_%: 10; Value1: Unknown; VDC_V: 16; TaMin_C: -55; TaMax_C: 85; Cap_Case: 0805
C67 C93 = 202R18W102KV4E: as C7 on sheet Pg4 ISO Power Supply, I2C & SPI Isolators
C82 C85 C87 C92 = GRM3195C1H273JA01D: CAP, CERM, 0.027uF, 50V, +/-5%, C0G/NP0, 1206; Manufacturer: MuRata; Polarized: N; CompType: Capacitor; U/M: EA; Cap_F: 0.000000027; Tolerance_%: 5; Value1: Unknown; VDC_V: 50; TaMin_C: -55; TaMax_C: 125
C84 C89 C90 C95 = 06031C272JAT2A: CAP, CERM, 2700pF, 100V, +/-5%, X7R, 0603; Manufacturer: AVX; Polarized: N; CompType: Capacitor; U/M: EA; Cap_F: 0.0000000027; Tolerance_%: 5; ESR_Ohm: 0.174; Value1: 0.174 ohm; VDC_V: 100; TaMin_C: -55; TaMax_C: 125
C88 C91 = EMK107BBJ106MA-T: CAP, CERM, 10uF, 16V, +/-20%, X5R, 0603; Manufacturer: Taiyo Yuden; Polarized: N; CompType: Capacitor; U/M: EA; Cap_F: 0.00001; Tolerance_%: 20; Value1: Unknown; VDC_V: 16; TaMin_C: -55; TaMax_C: 85
C94 = EMK107B7105KA-T: CAP, CERM, 1uF, 16V, +/-10%, X7R, 0603; Manufacturer: Taiyo Yuden; Polarized: N; CompType: Capacitor; U/M: EA; Cap_F: 0.000001; Tolerance_%: 10; Value1: Unknown; VDC_V: 16; TaMin_C: -55; TaMax_C: 85
D2 = SMBJ18CA: TVS 18 VOLT 600 WATT BI-DIR SMB; Manufacturer: Littelfuse Inc
D11 D14 = CDSOD323-T15SC: Diode, TVS, ARRAY, 19V, SOD323; Manufacturer: Bourns Inc.
D15 D17 = CDSOD323-T15SC: Diode, TVS, ARRAY, 19V, SOD323; Manufacturer: Bourns Inc.; Value: 19
FB3 = MMZ1608B102C: as L1 on sheet Pg5 LDO
J1 J4 = 282834-2: Terminal Block, 2x1, 2.54mm, TH; Manufacturer: TE Connectivity; SymbolCreator: a0412235; U/M: EA
J3 = 1725711: Terminal Block, 8x1, 2.54 mm, TH; Manufacturer: Phoenix Contact; SymbolCreator: a0411947; U/M: EA
R20 R29 R35 R44 = MMA02040C1000FB300: RES 100 OHM .4W 1% 0204 MELF; Manufacturer: Vishay Beyschlag; CompType: Resistor; Power_W: 0.5
R21 R30 R37 R50 = RG2012P-201-B-T5: RES, 200 ohm, 0.1%, 0.125W, 0805; Manufacturer: Susumu Co Ltd; CompType: Resistor; Value_Code: 200R; Tolerance_%: 0.1; Power_W: 0.125; VDC_V: 100; TempCo: 25 ppm/C; EIA_Code: E192; U/M: EA
R25 R36 R39 R53 = CRCW06031K00FKEA: RES, 1.00k ohm, 1%, 0.1W, 0603; Manufacturer: Vishay-Dale; CompType: Resistor; Res_ohm: 1000; Value_Code: 1k00; Tolerance_%: 1; Power_W: 0.1; VDC_V: 75; TempCo: 100 ppm/C; EIA_Code: E96; U/M: EA
R26 R34 R43 R56 = CRCW0402680RJNED: RES, 680 ohm, 5%, 0.063W, 0402; Manufacturer: Vishay-Dale; CompType: Resistor; Value_Code: 680R; Tolerance_%: 5; Power_W: 0.063; VDC_V: 50; TempCo: 200 ppm/C; EIA_Code: E24; U/M: EA
R28 R33 R41 R54 = CRCW04020000Z0ED: RES, 0 ohm, 5%, 0.063W, 0402; Manufacturer: Vishay-Dale; CompType: Resistor; Value_Code: 0000; Tolerance_%: 5; Power_W: 0.063; VDC_V: 50; TempCo: 200 ppm/C; EIA_Code: E24; U/M: EA
R31 R32 R46 R52 = CRCW04021K10FKED: RES, 1.10k ohm, 1%, 0.063W, 0402; Manufacturer: Vishay-Dale; CompType: Resistor; Res_ohm: 1100; Value_Code: 1k10; Tolerance_%: 1; Power_W: 0.063; VDC_V: 50; TempCo: 100 ppm/C; EIA_Code: E96; U/M: EA
R38 = CRCW060310R0FKEA: RES, 10.0 ohm, 1%, 0.1W, 0603; Manufacturer: Vishay-Dale; CompType: Resistor; Res_ohm: 10; Value_Code: 10R0; Tolerance_%: 1; Power_W: 0.1; VDC_V: 75; TempCo: 100 ppm/C; EIA_Code: E96; U/M: EA
R45 = CRCW040249R9FKED: RES, 49.9 ohm, 1%, 0.063W, 0402; Manufacturer: Vishay-Dale; CompType: Resistor; Value_Code: 49R9; Tolerance_%: 1; Power_W: 0.063; VDC_V: 50; TempCo: 100 ppm/C; EIA_Code: E96; U/M: EA
R63 R64 R68 R70 = CRCW12060000Z0EAHP: RES 0.0 OHM .5W JUMP 1206 SMD; Manufacturer: Vishay Dale; CompType: Resistor; Power_W: 0.5; Value2: 0.5W; VDC_V: 200
R67 R69 R74 R78 = CRCW040210M0FKED: RES, 10.0Meg ohm, 1%, 0.063W, 0402; Manufacturer: Vishay-Dale; CompType: Resistor; Res_ohm: 10000000; Value_Code: 10M0; Tolerance_%: 1; Power_W: 0.063; VDC_V: 50; TempCo: 100 ppm/C; EIA_Code: E96; U/M: EA
R71 R72 = CRCW040247K0JNED: RES, 47k ohm, 5%, 0.063W, 0402; Manufacturer: Vishay-Dale; CompType: Resistor; Res_ohm: 47000; Value_Code: 47k0; Tolerance_%: 5; Power_W: 0.063; VDC_V: 50; TempCo: 200 ppm/C; EIA_Code: E24; U/M: EA
R73 R75 = RT0603BRD0747KL: RES, 47.0k ohm, 0.1%, 0.1W, 0603; Manufacturer: Yageo America; CompType: Resistor; Res_ohm: 47000; Value_Code: 47k0; Tolerance_%: 0.1; VDC_V: 75; TempCo: 25 ppm/C; EIA_Code: E192; U/M: EA
TP18 TP23 TP28 = TP-040_RND: as TP12 on sheet Pg3 Interboard conn, HS & EEPROM
U8 U10 U14 U16 = TLP3123(F): PHOTORELAY MOSFET 1A 4-SOP; Manufacturer: Toshiba Semiconductor and Storage; Area: 81900
U13 = ADS8688DBT: 16 bit 400KSPS 8 Channel SAR ADC; Manufacturer: TI; Alternate Manufacturer: None; SymbolCreator: a0393903; CompType: ADC IC; U/M: EA, IN, or GM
